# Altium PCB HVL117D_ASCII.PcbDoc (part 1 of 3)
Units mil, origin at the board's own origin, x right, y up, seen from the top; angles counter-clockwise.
Board outline 2004.03 x 2004.03 mil, 6 copper layers (Top Layer, InternalPlane1, MidLayer1, InternalPlane2, MidLayer2, Bottom Layer), stack 60.56 mil thick; 218 components, 157 nets, 658 pads, 273 vias.
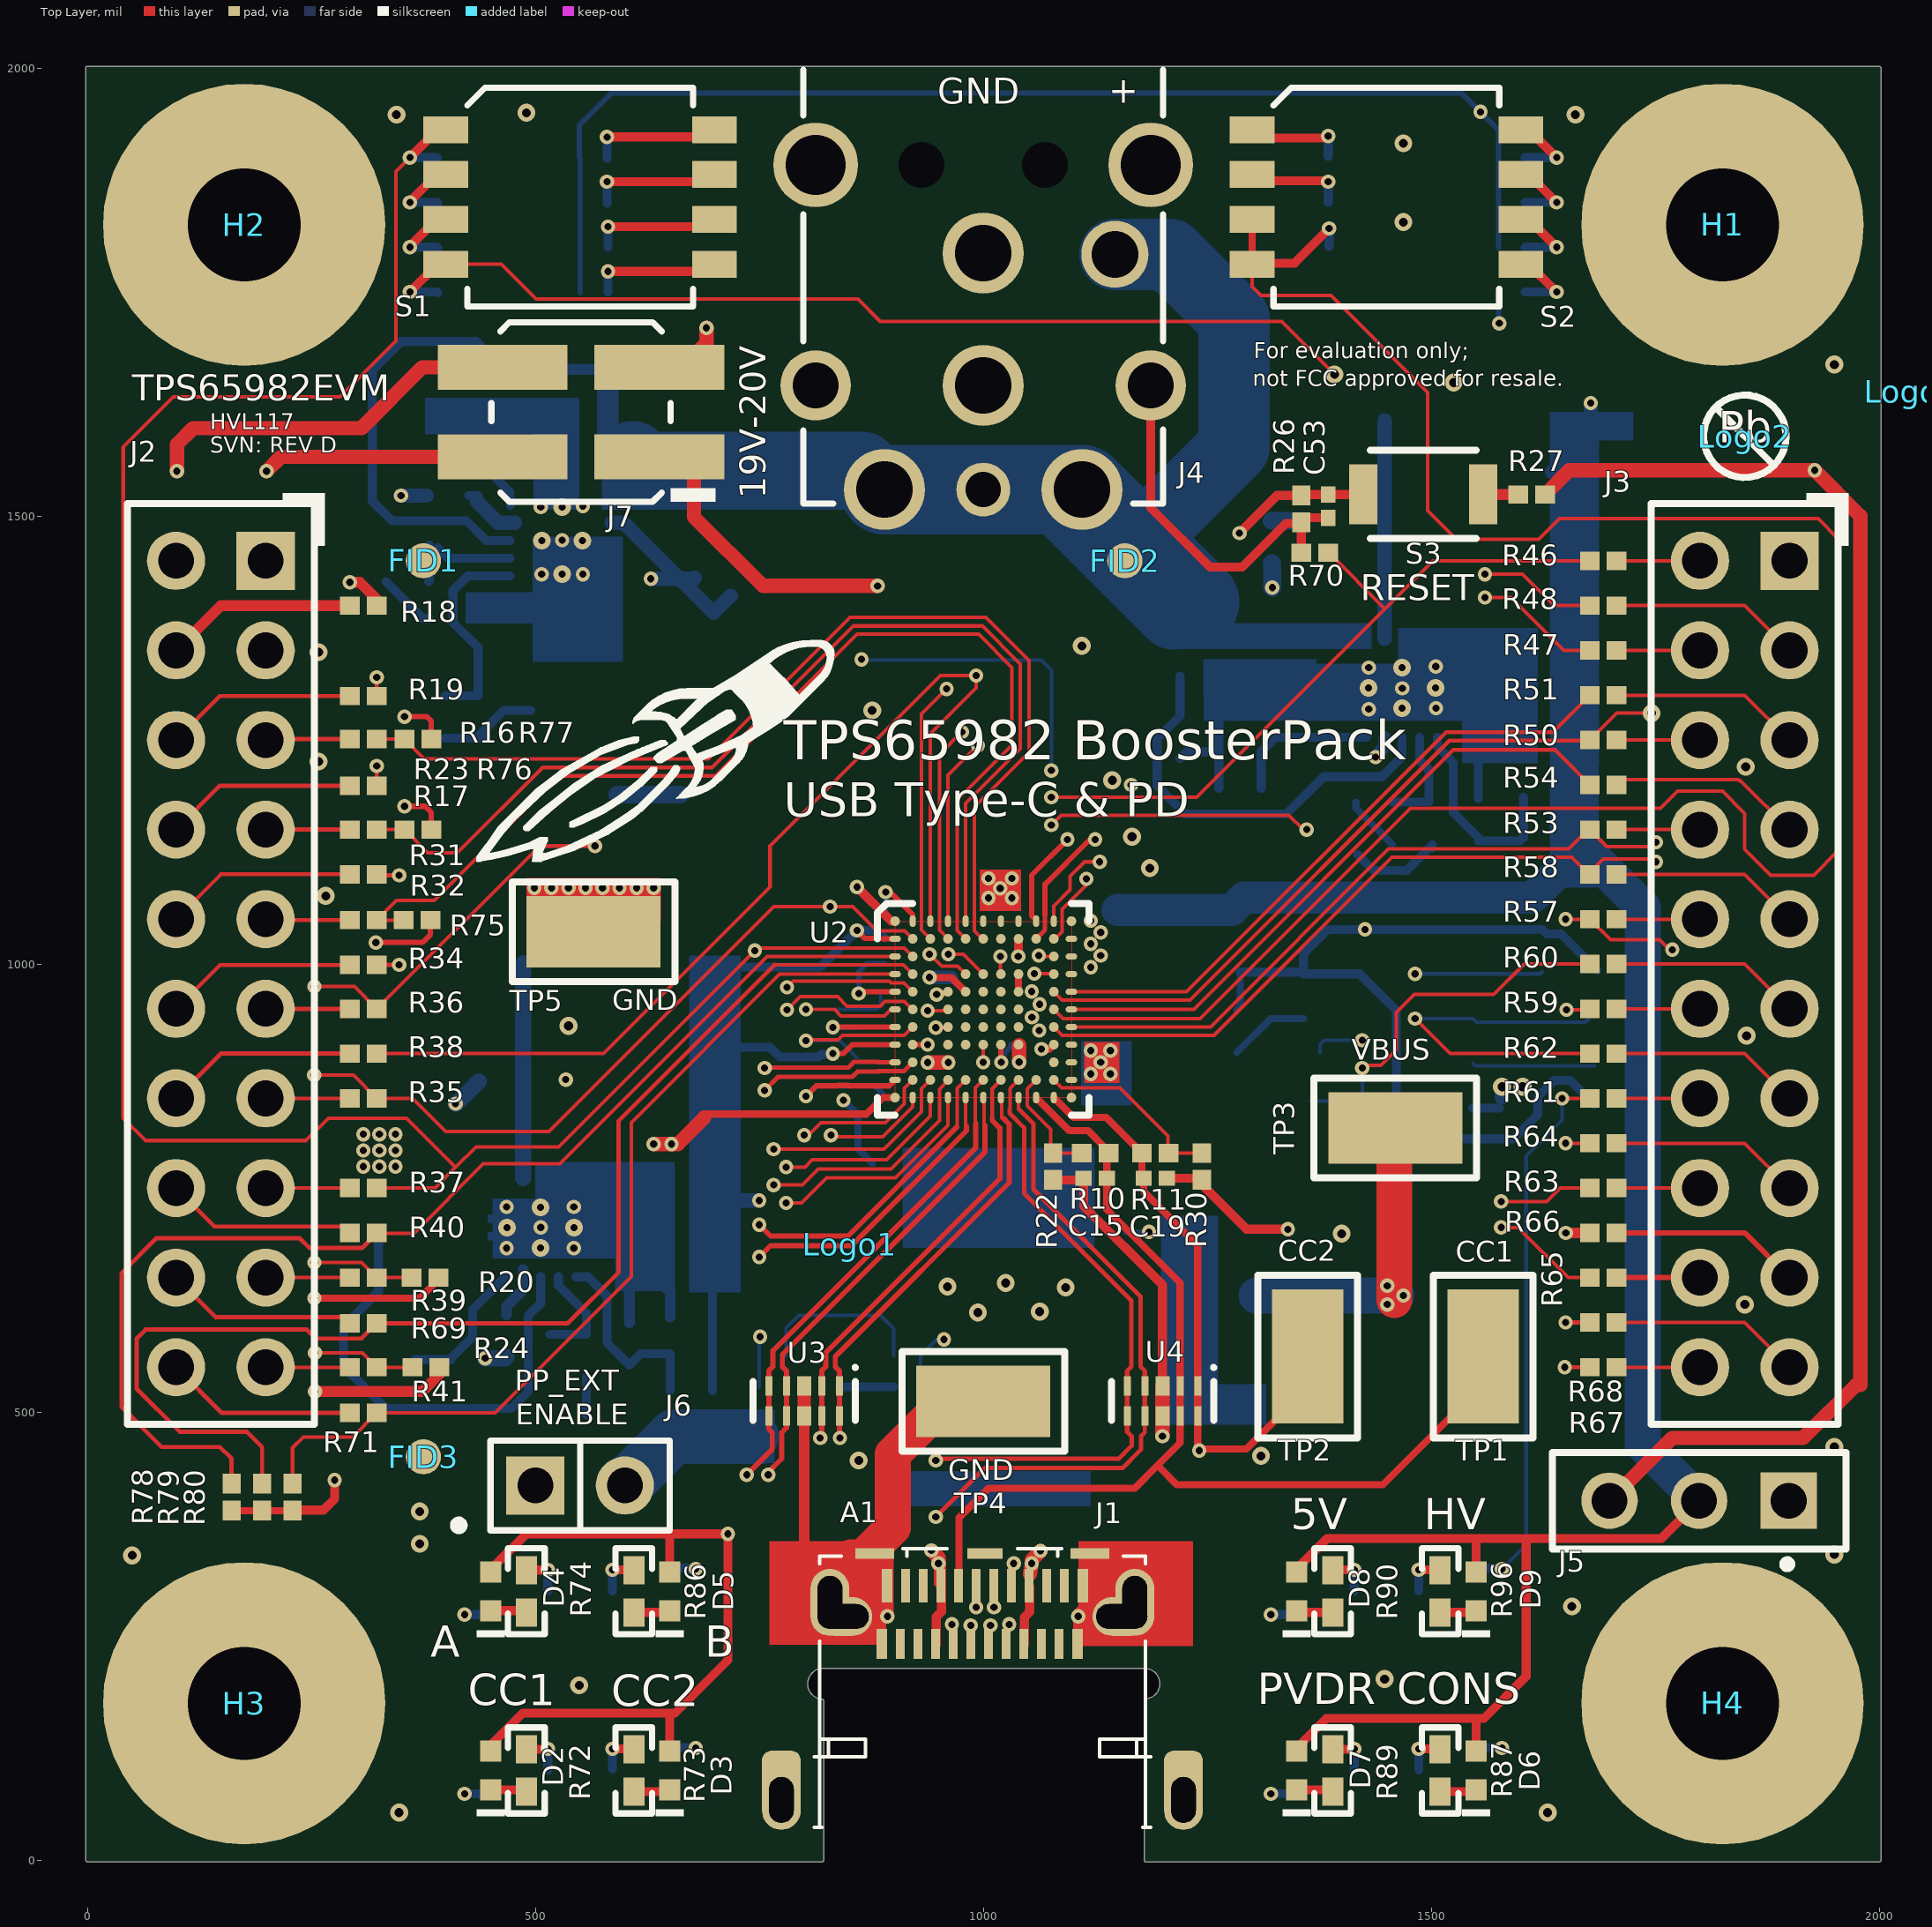
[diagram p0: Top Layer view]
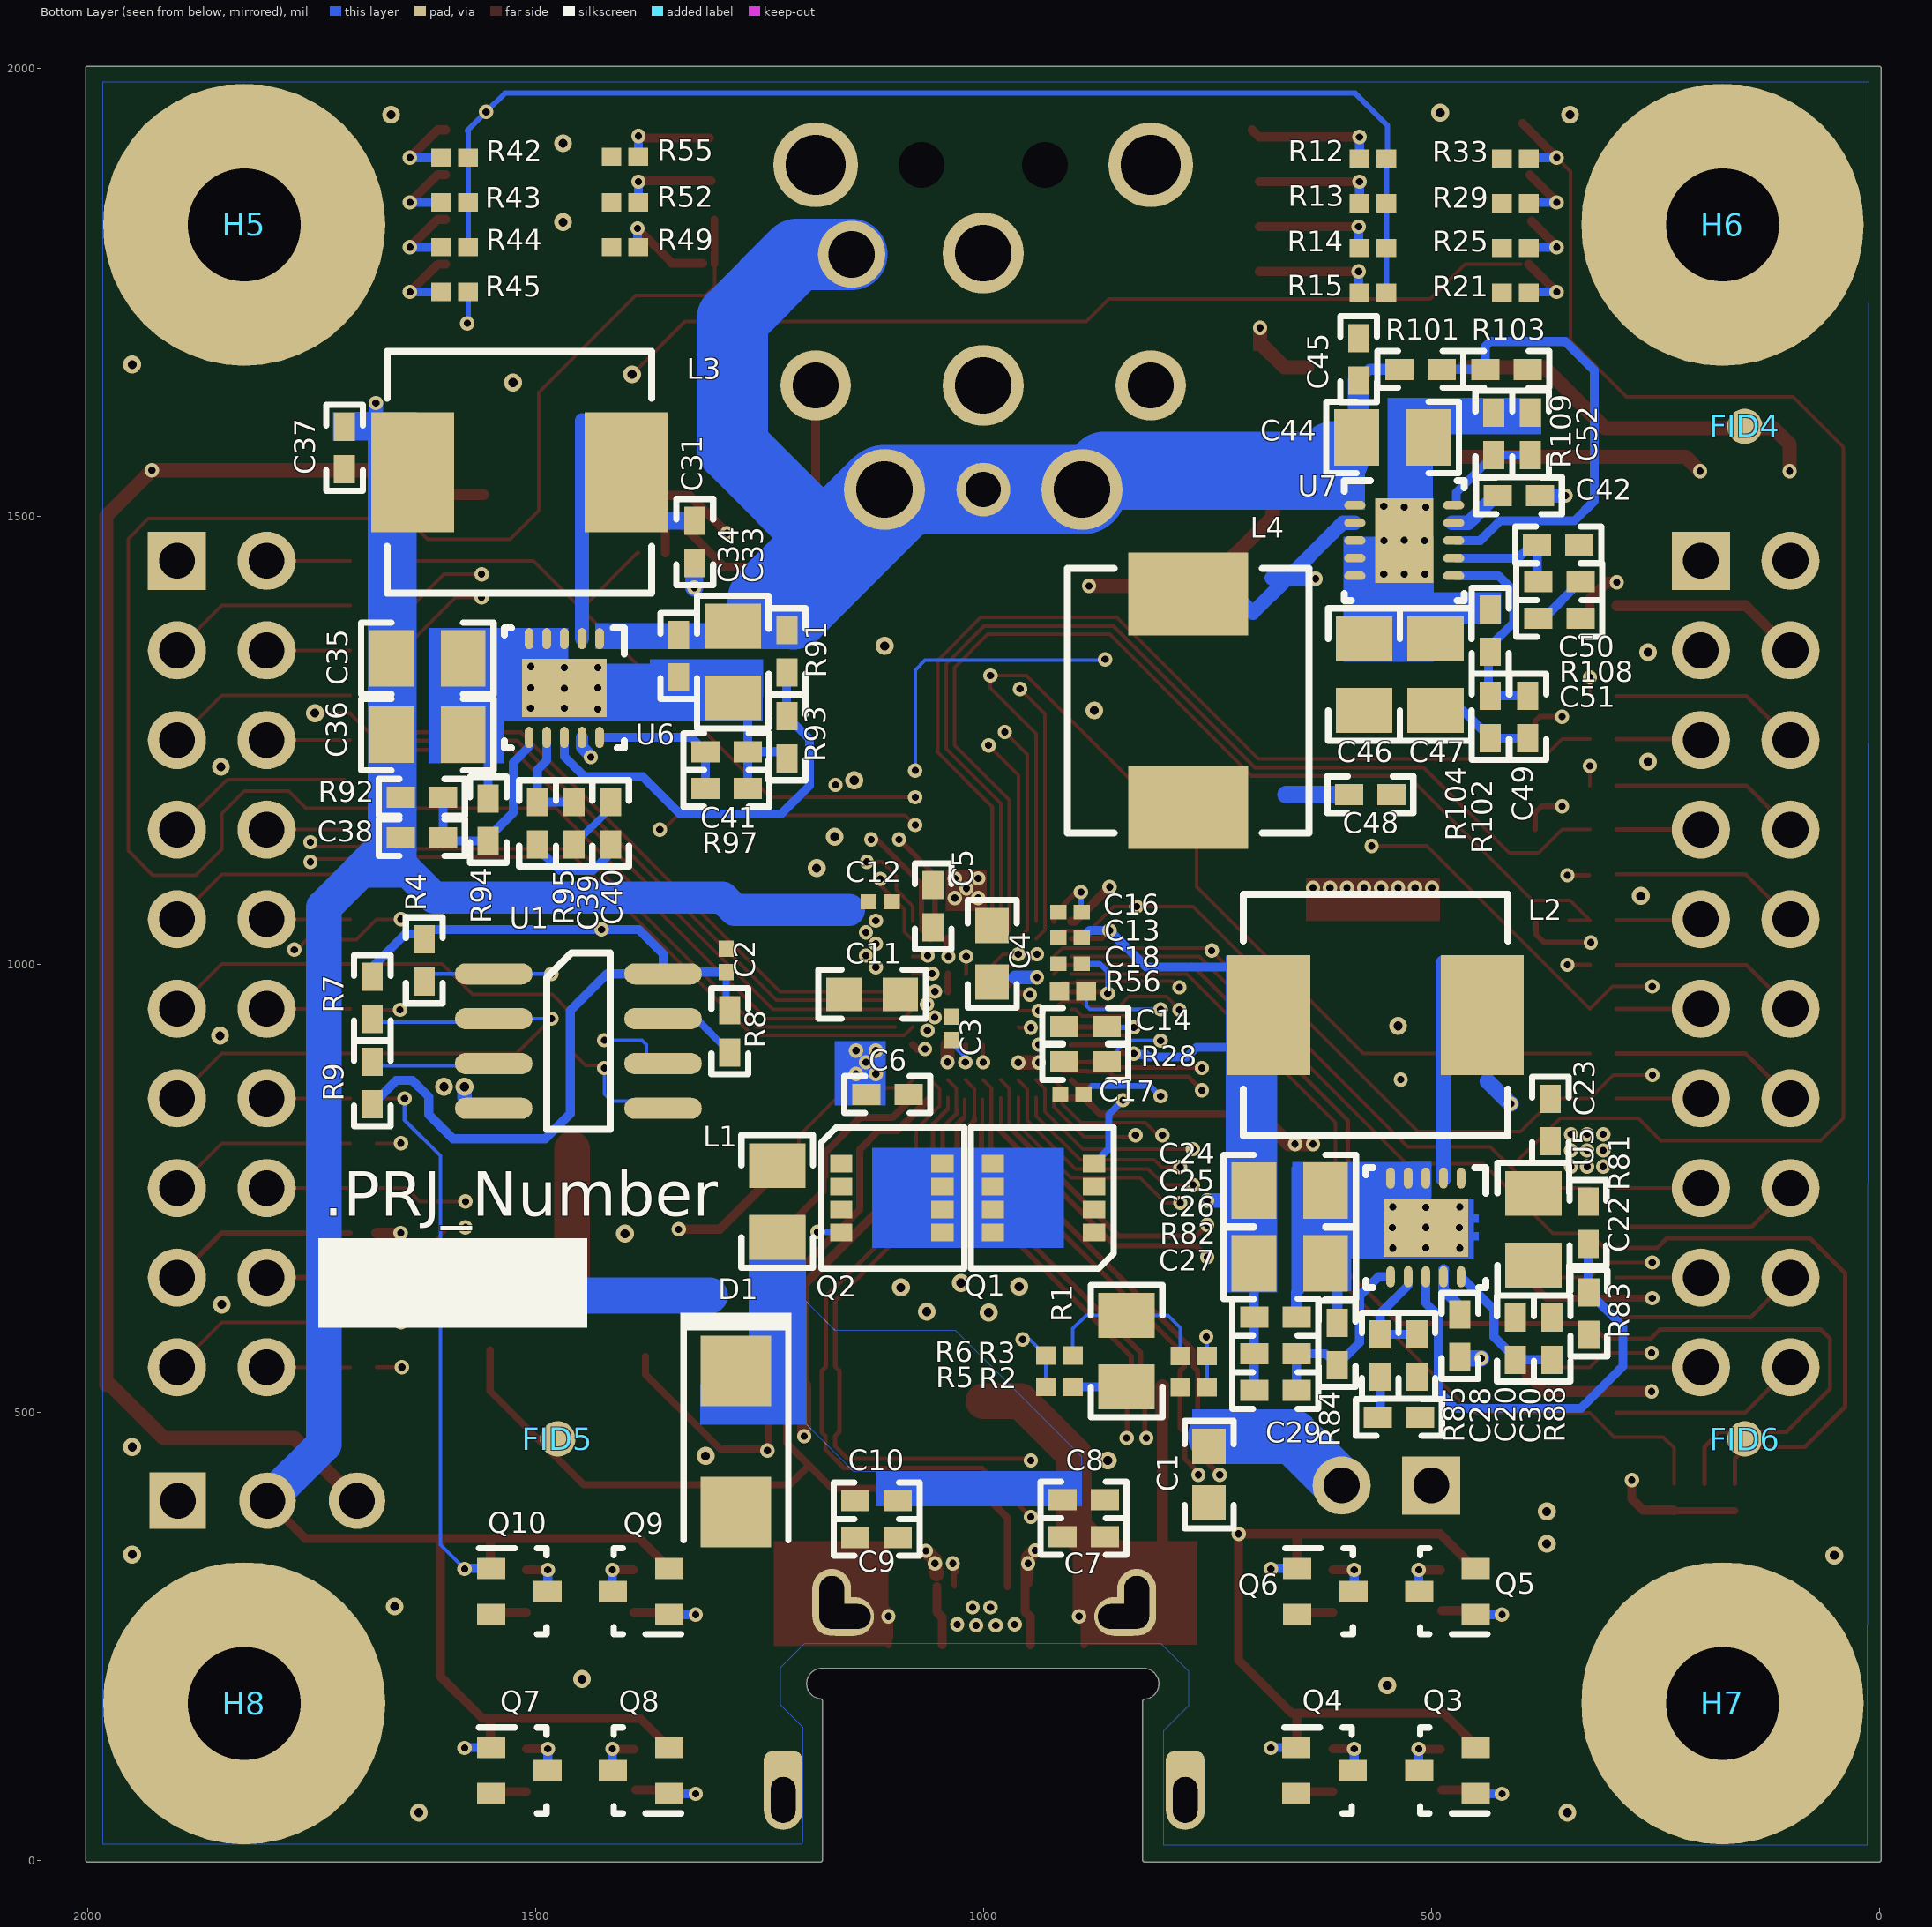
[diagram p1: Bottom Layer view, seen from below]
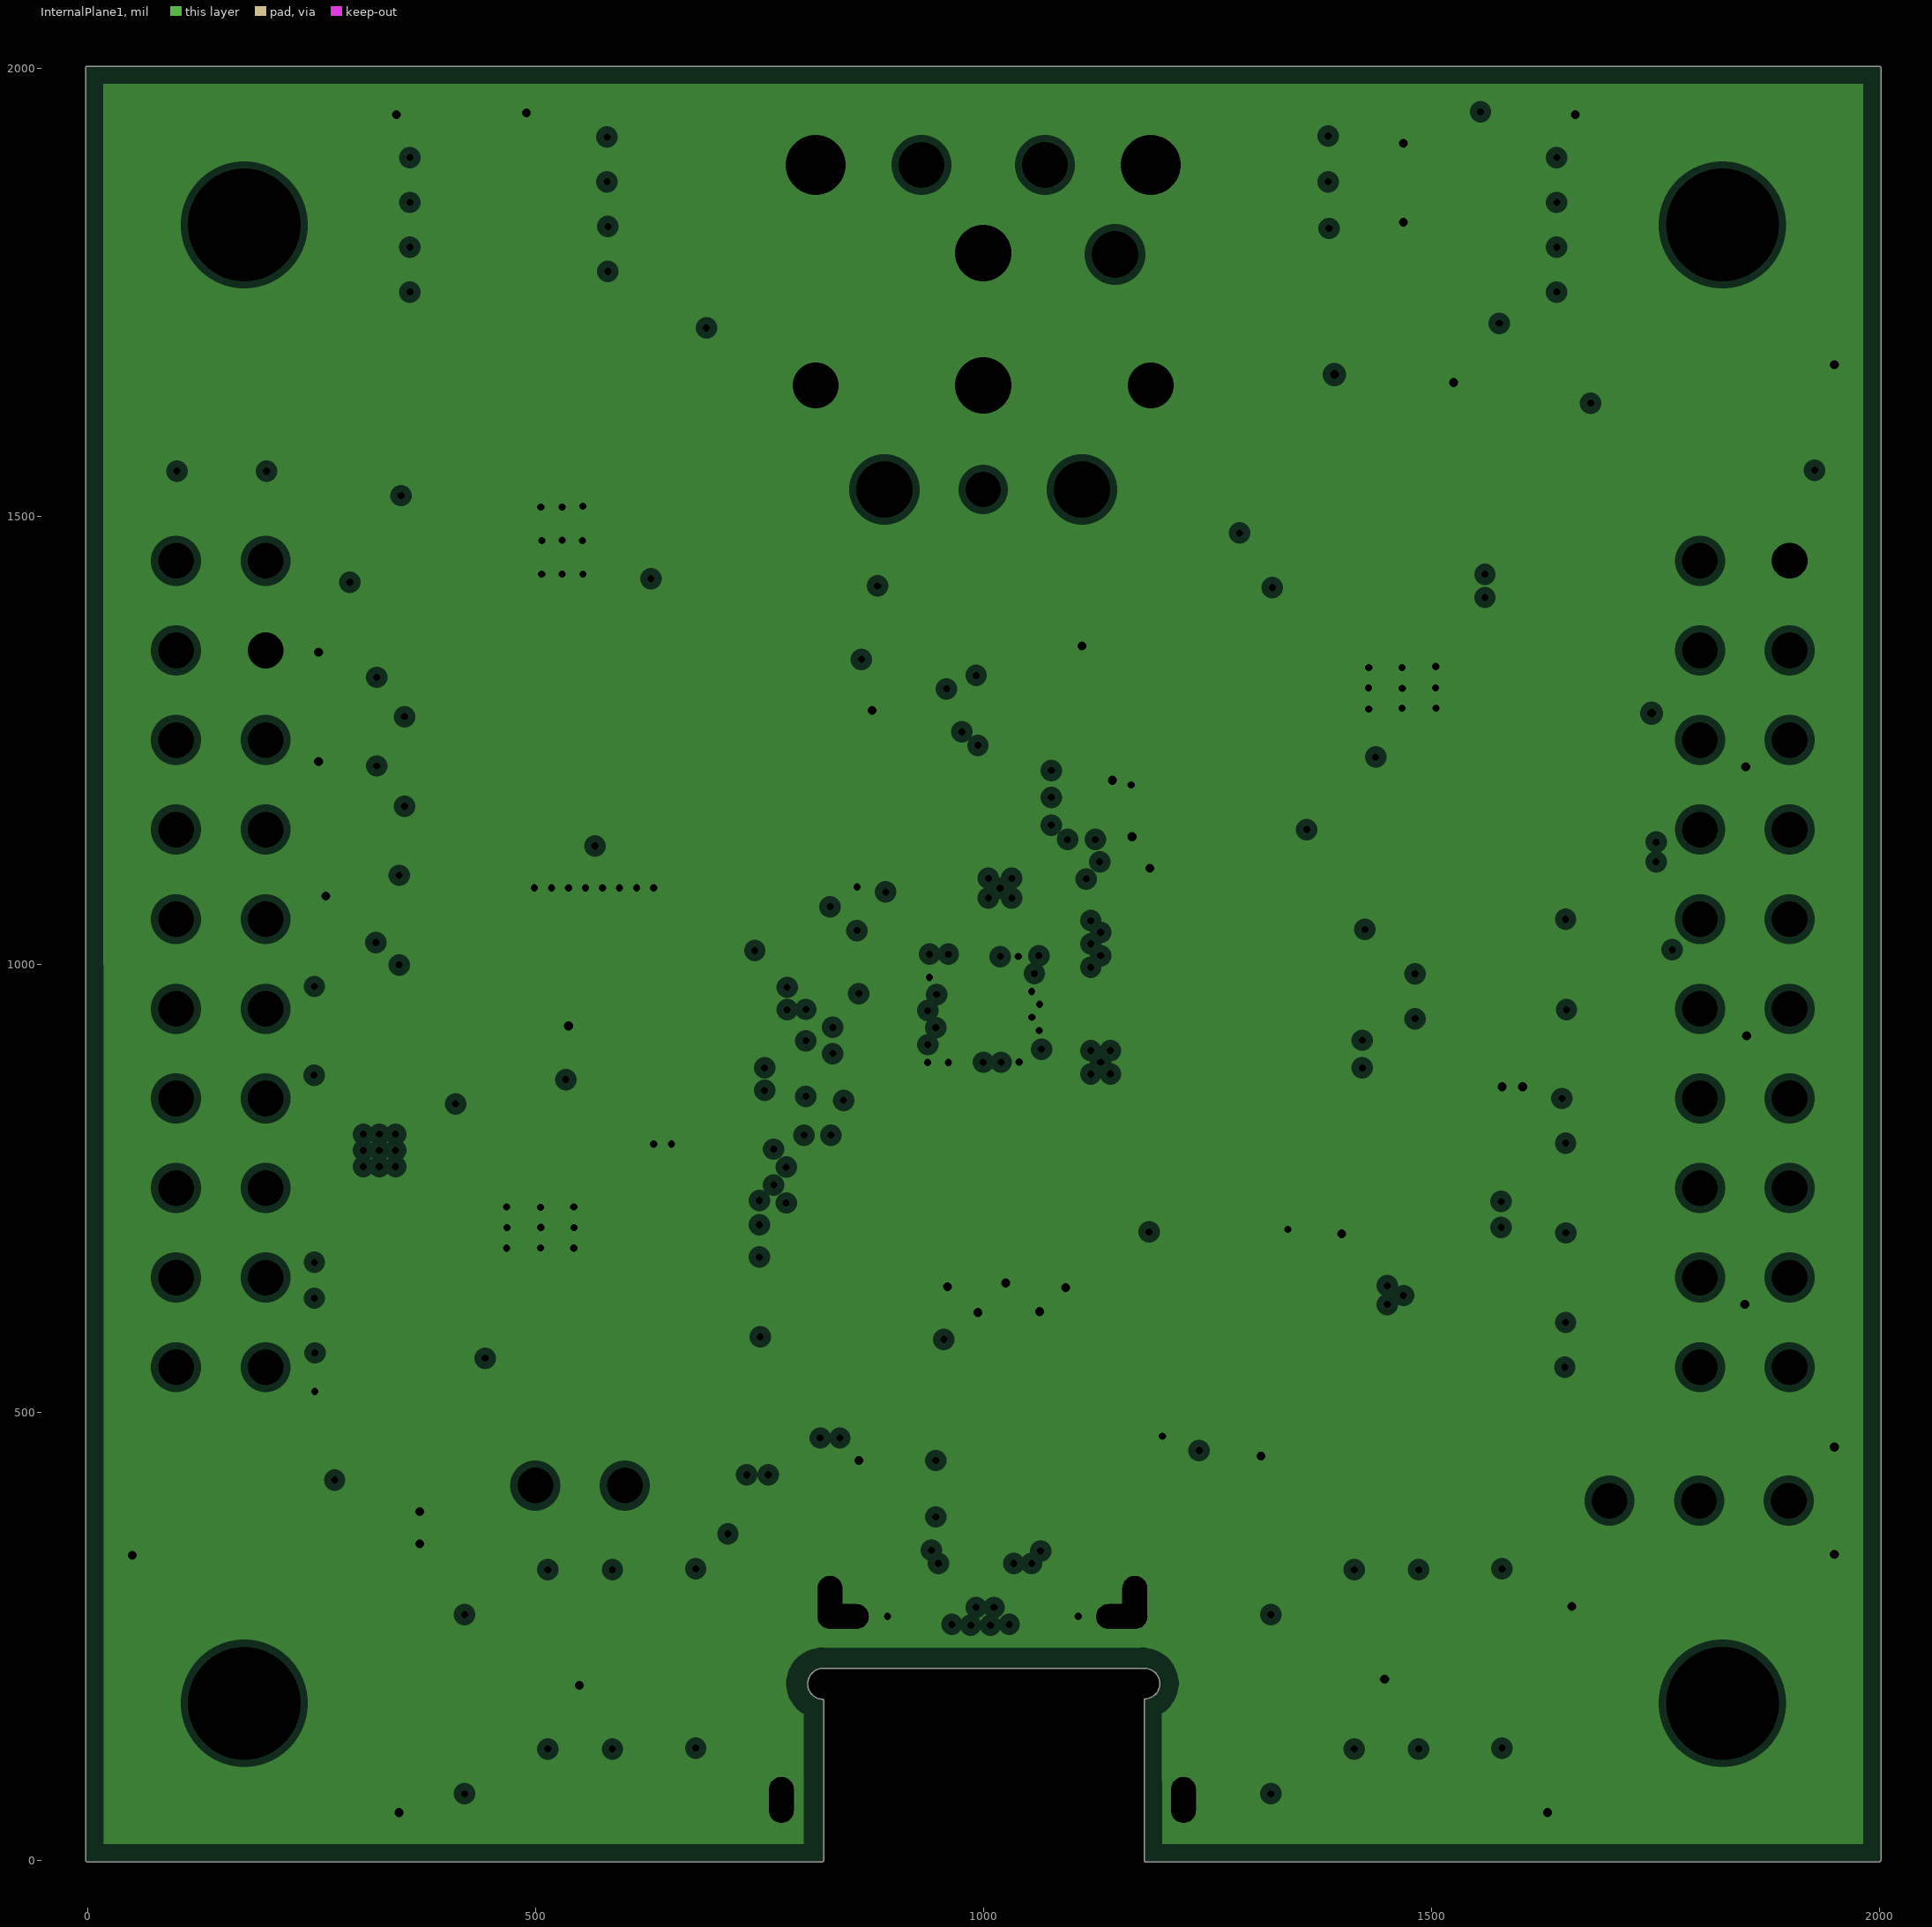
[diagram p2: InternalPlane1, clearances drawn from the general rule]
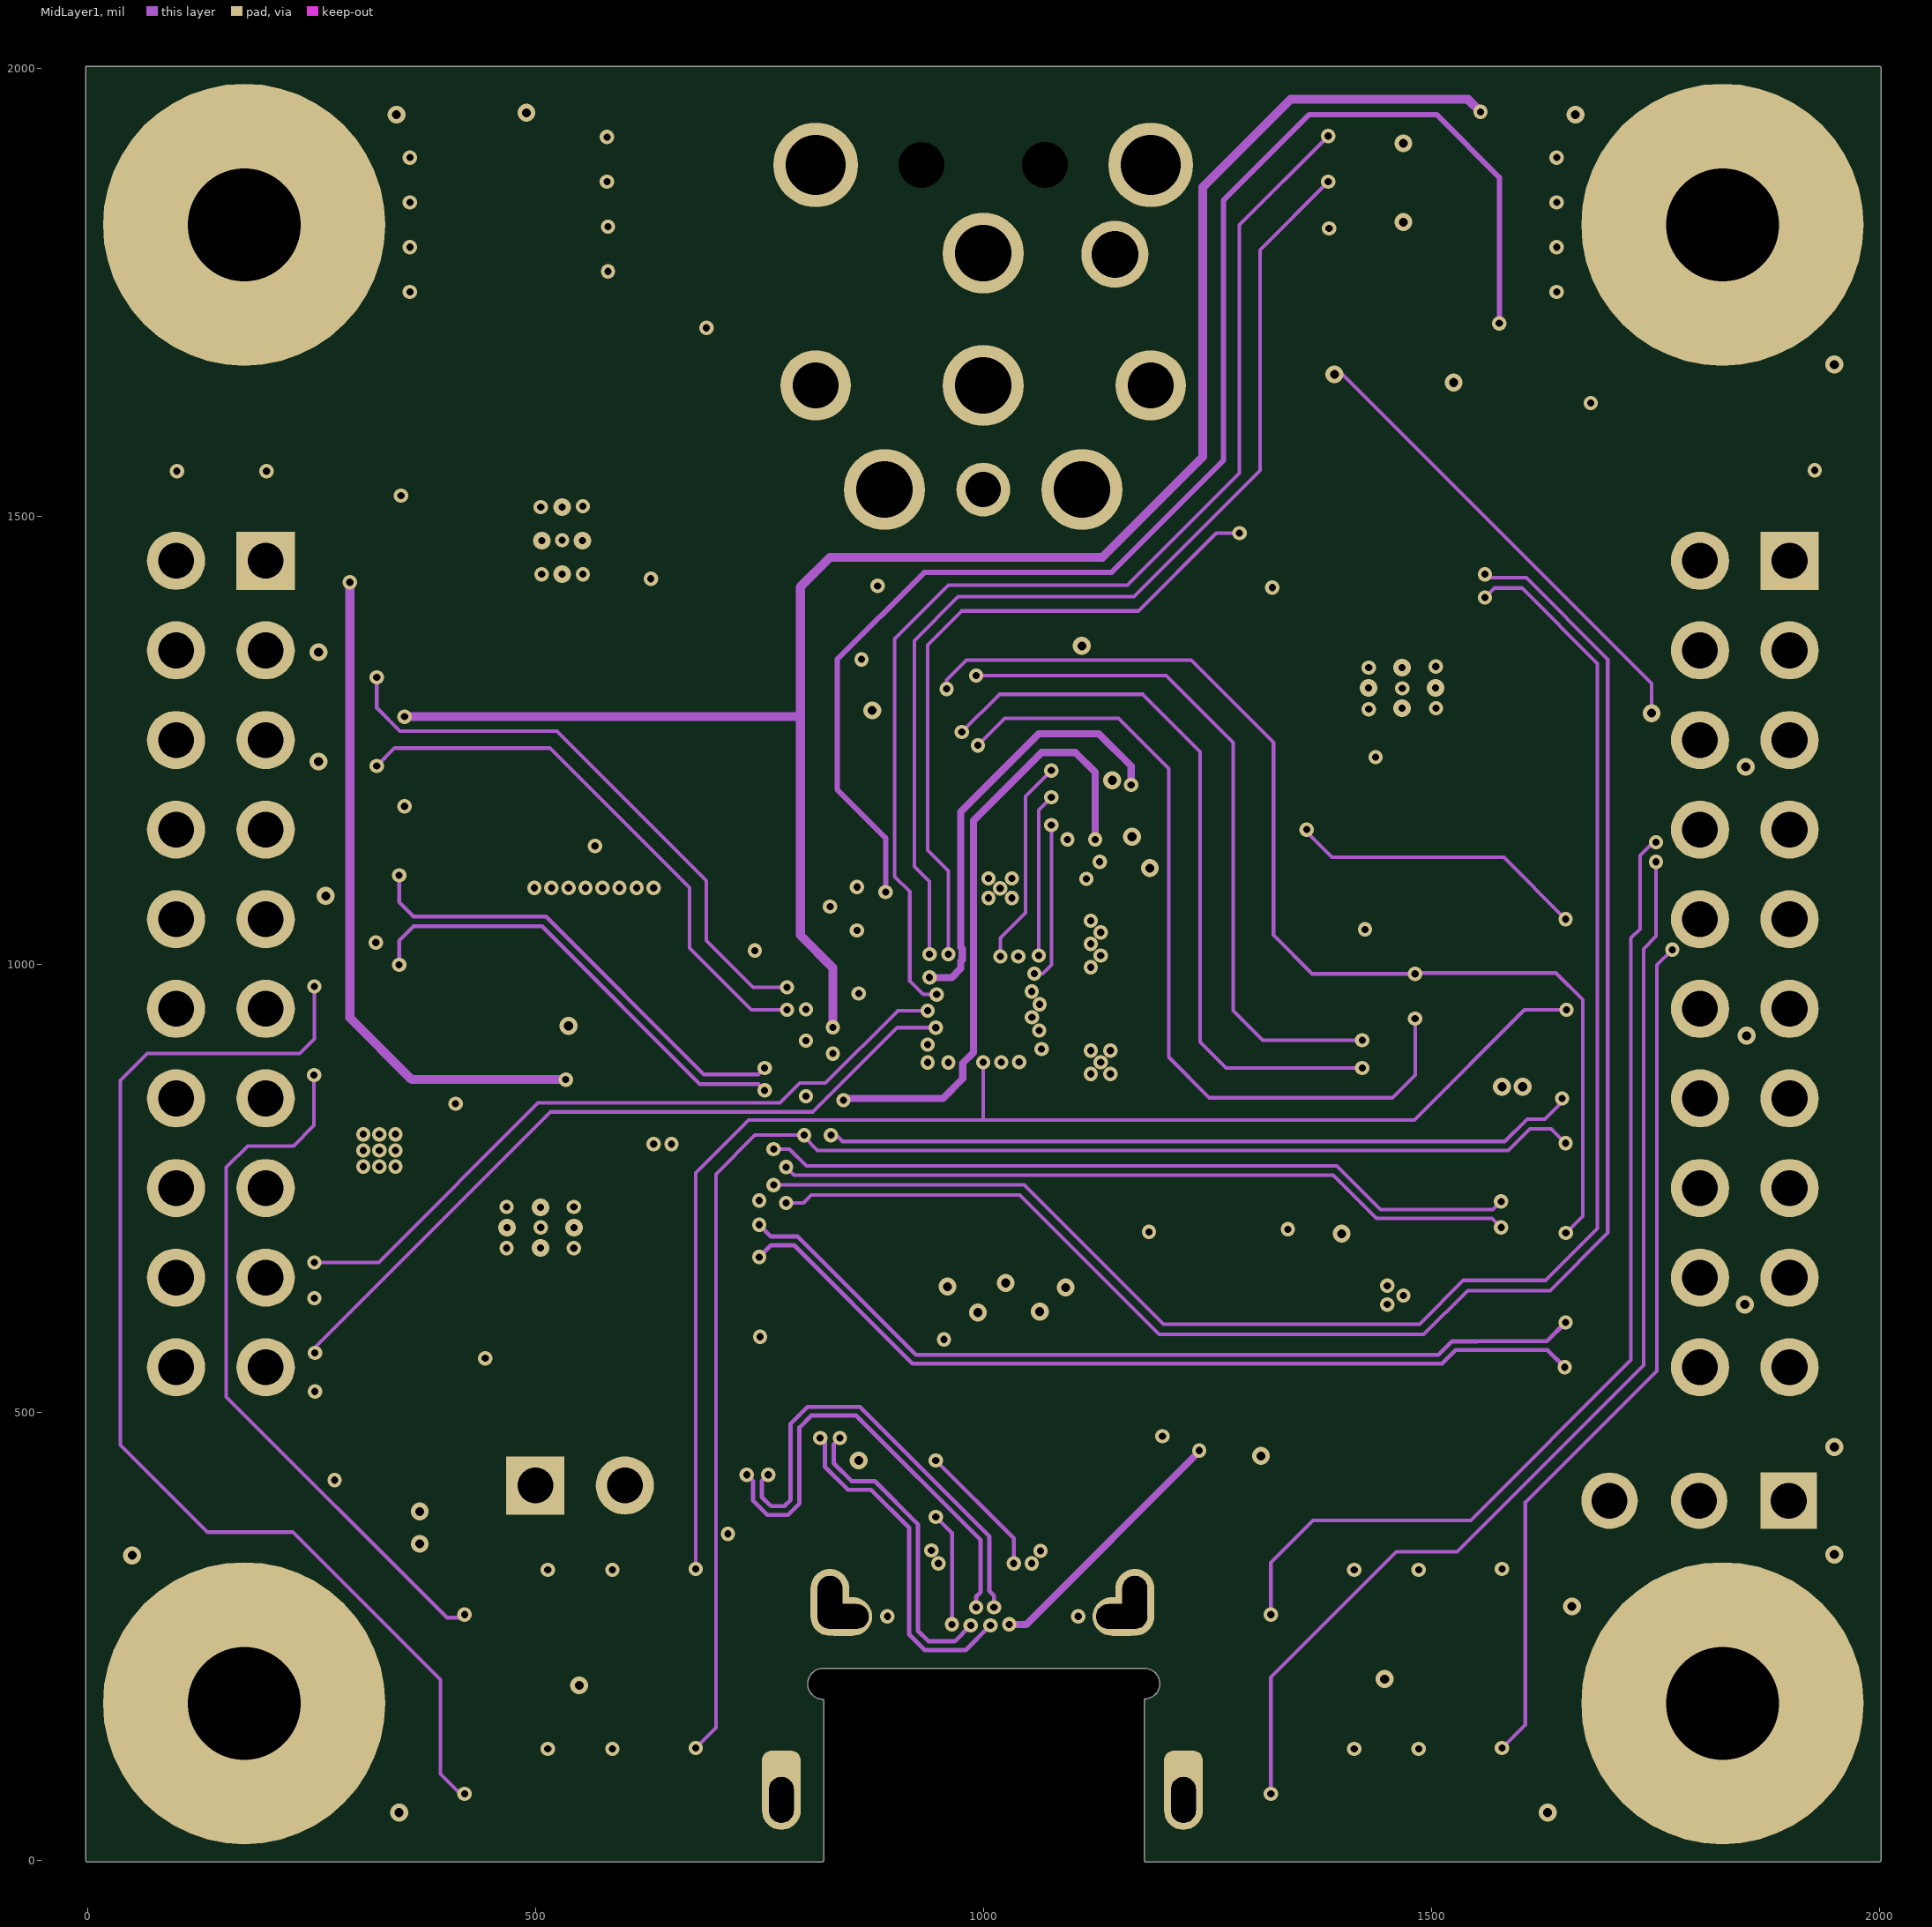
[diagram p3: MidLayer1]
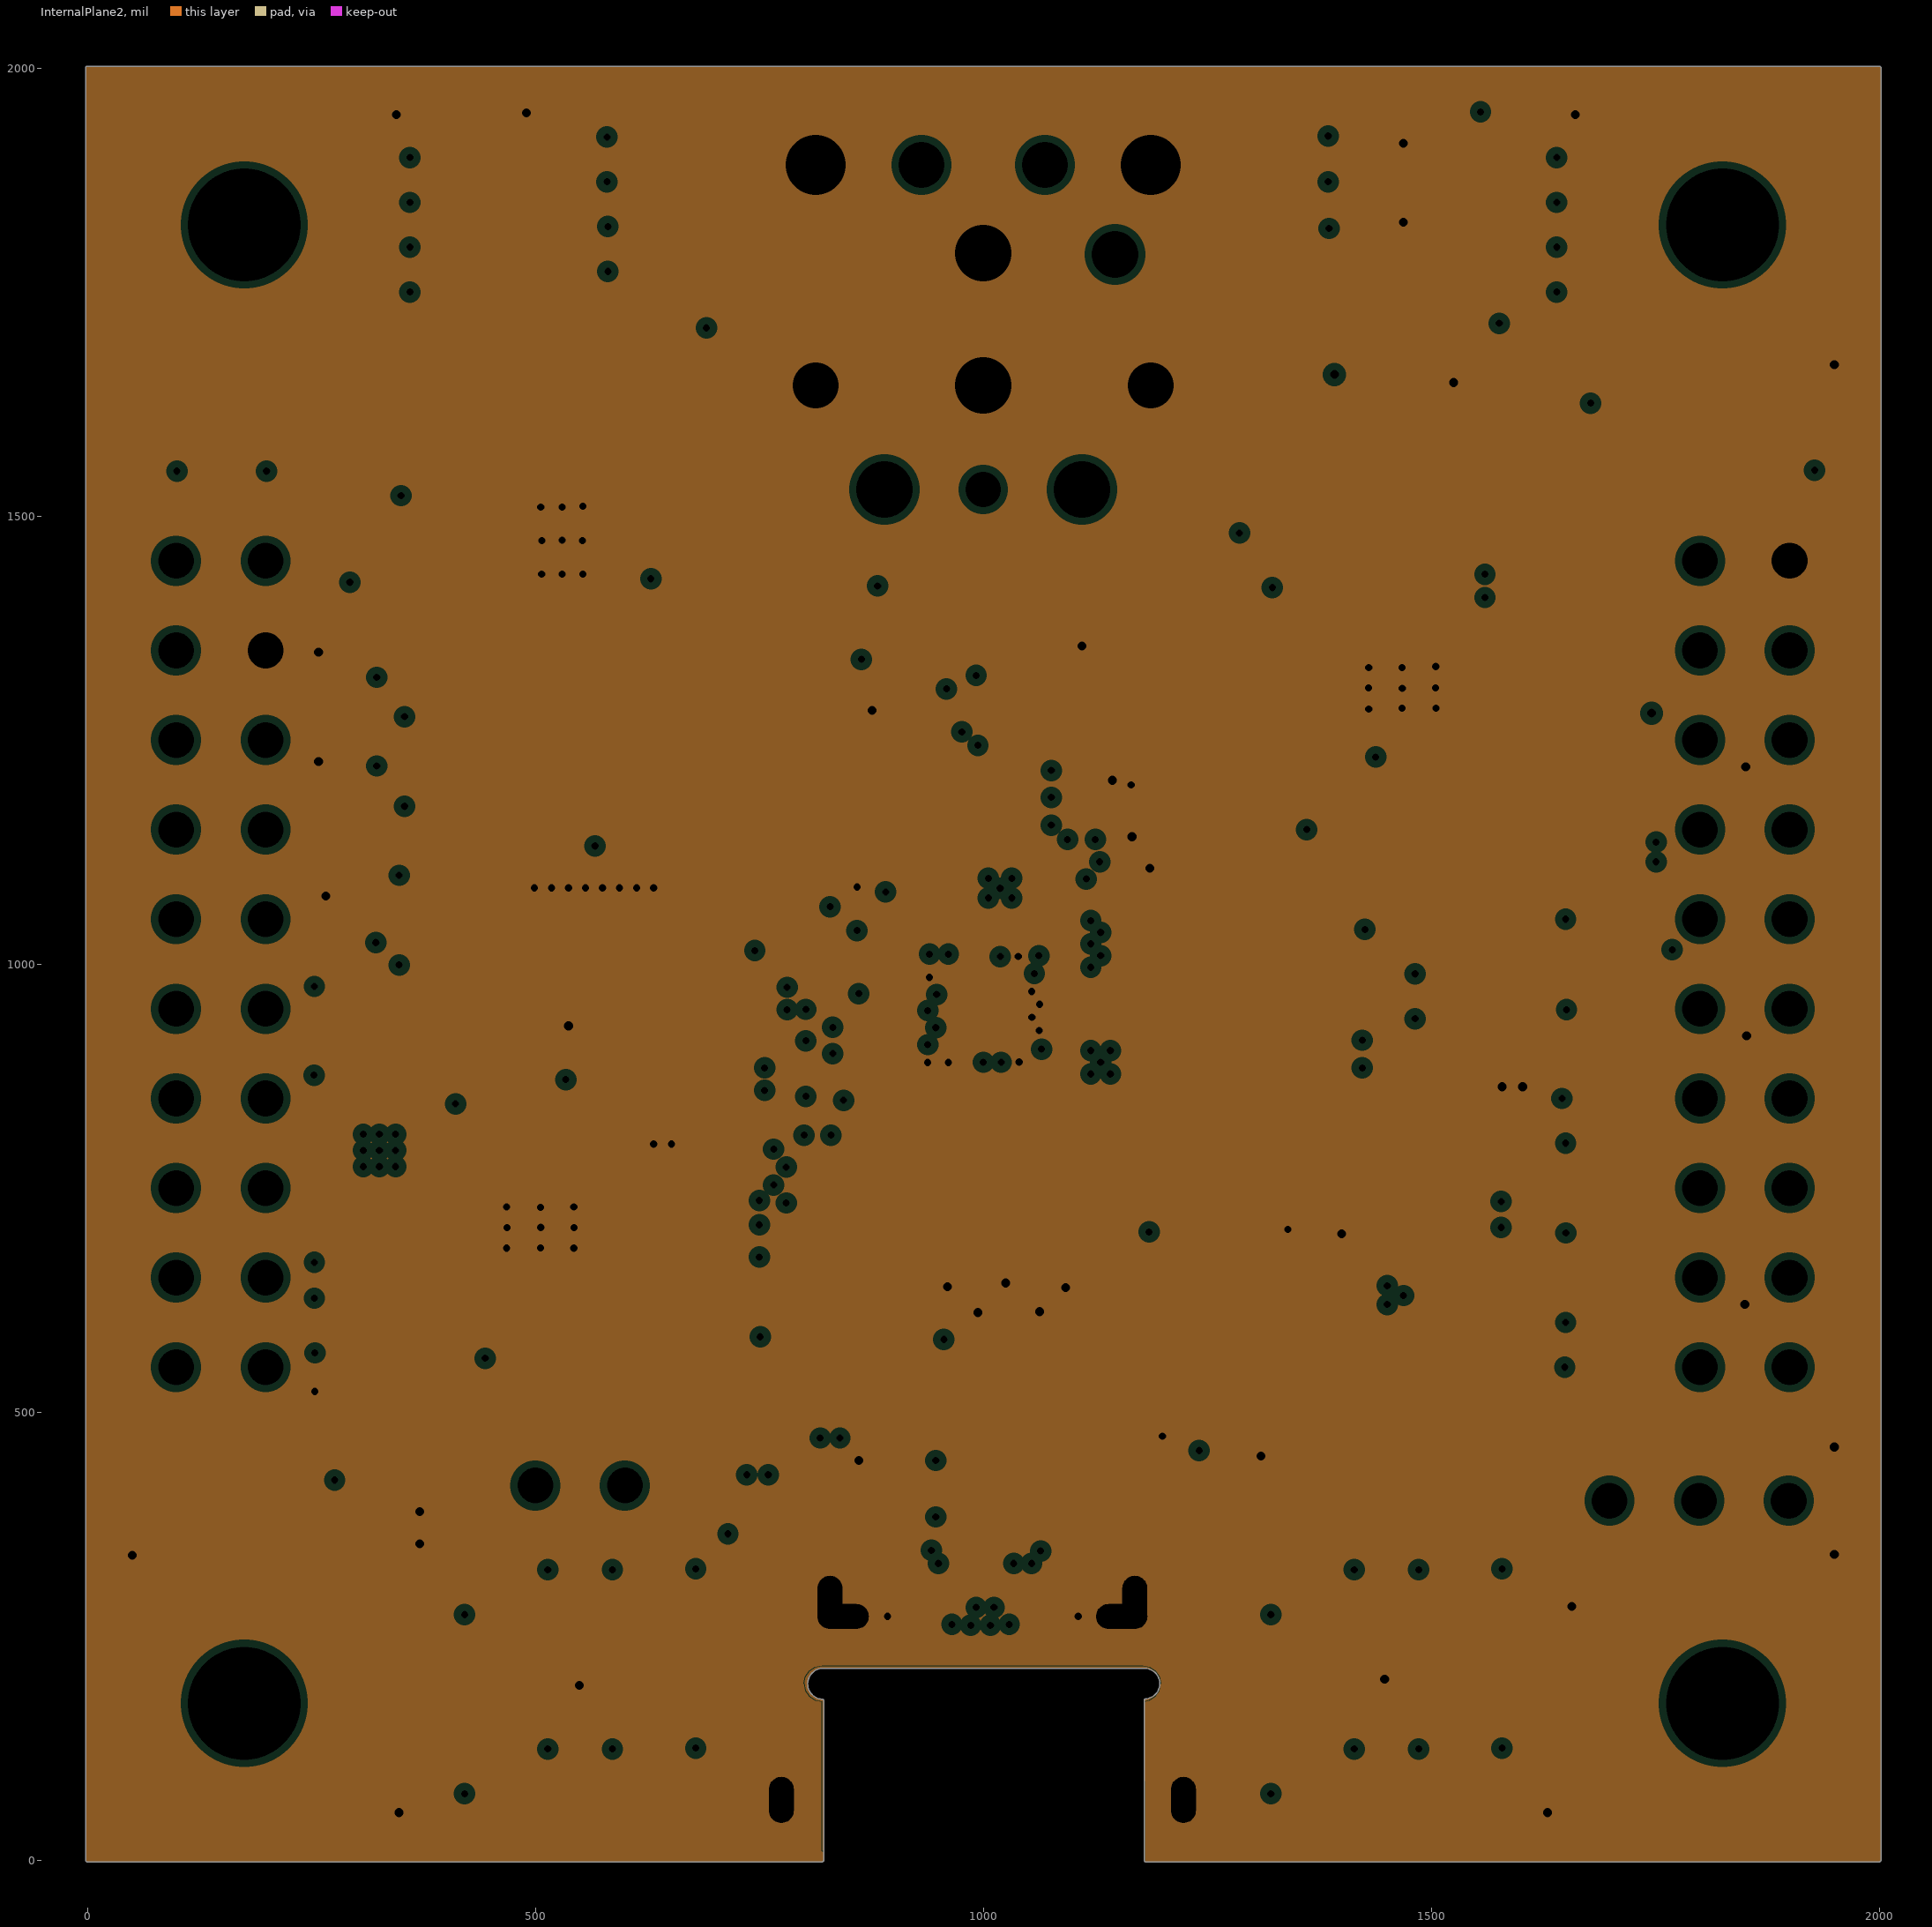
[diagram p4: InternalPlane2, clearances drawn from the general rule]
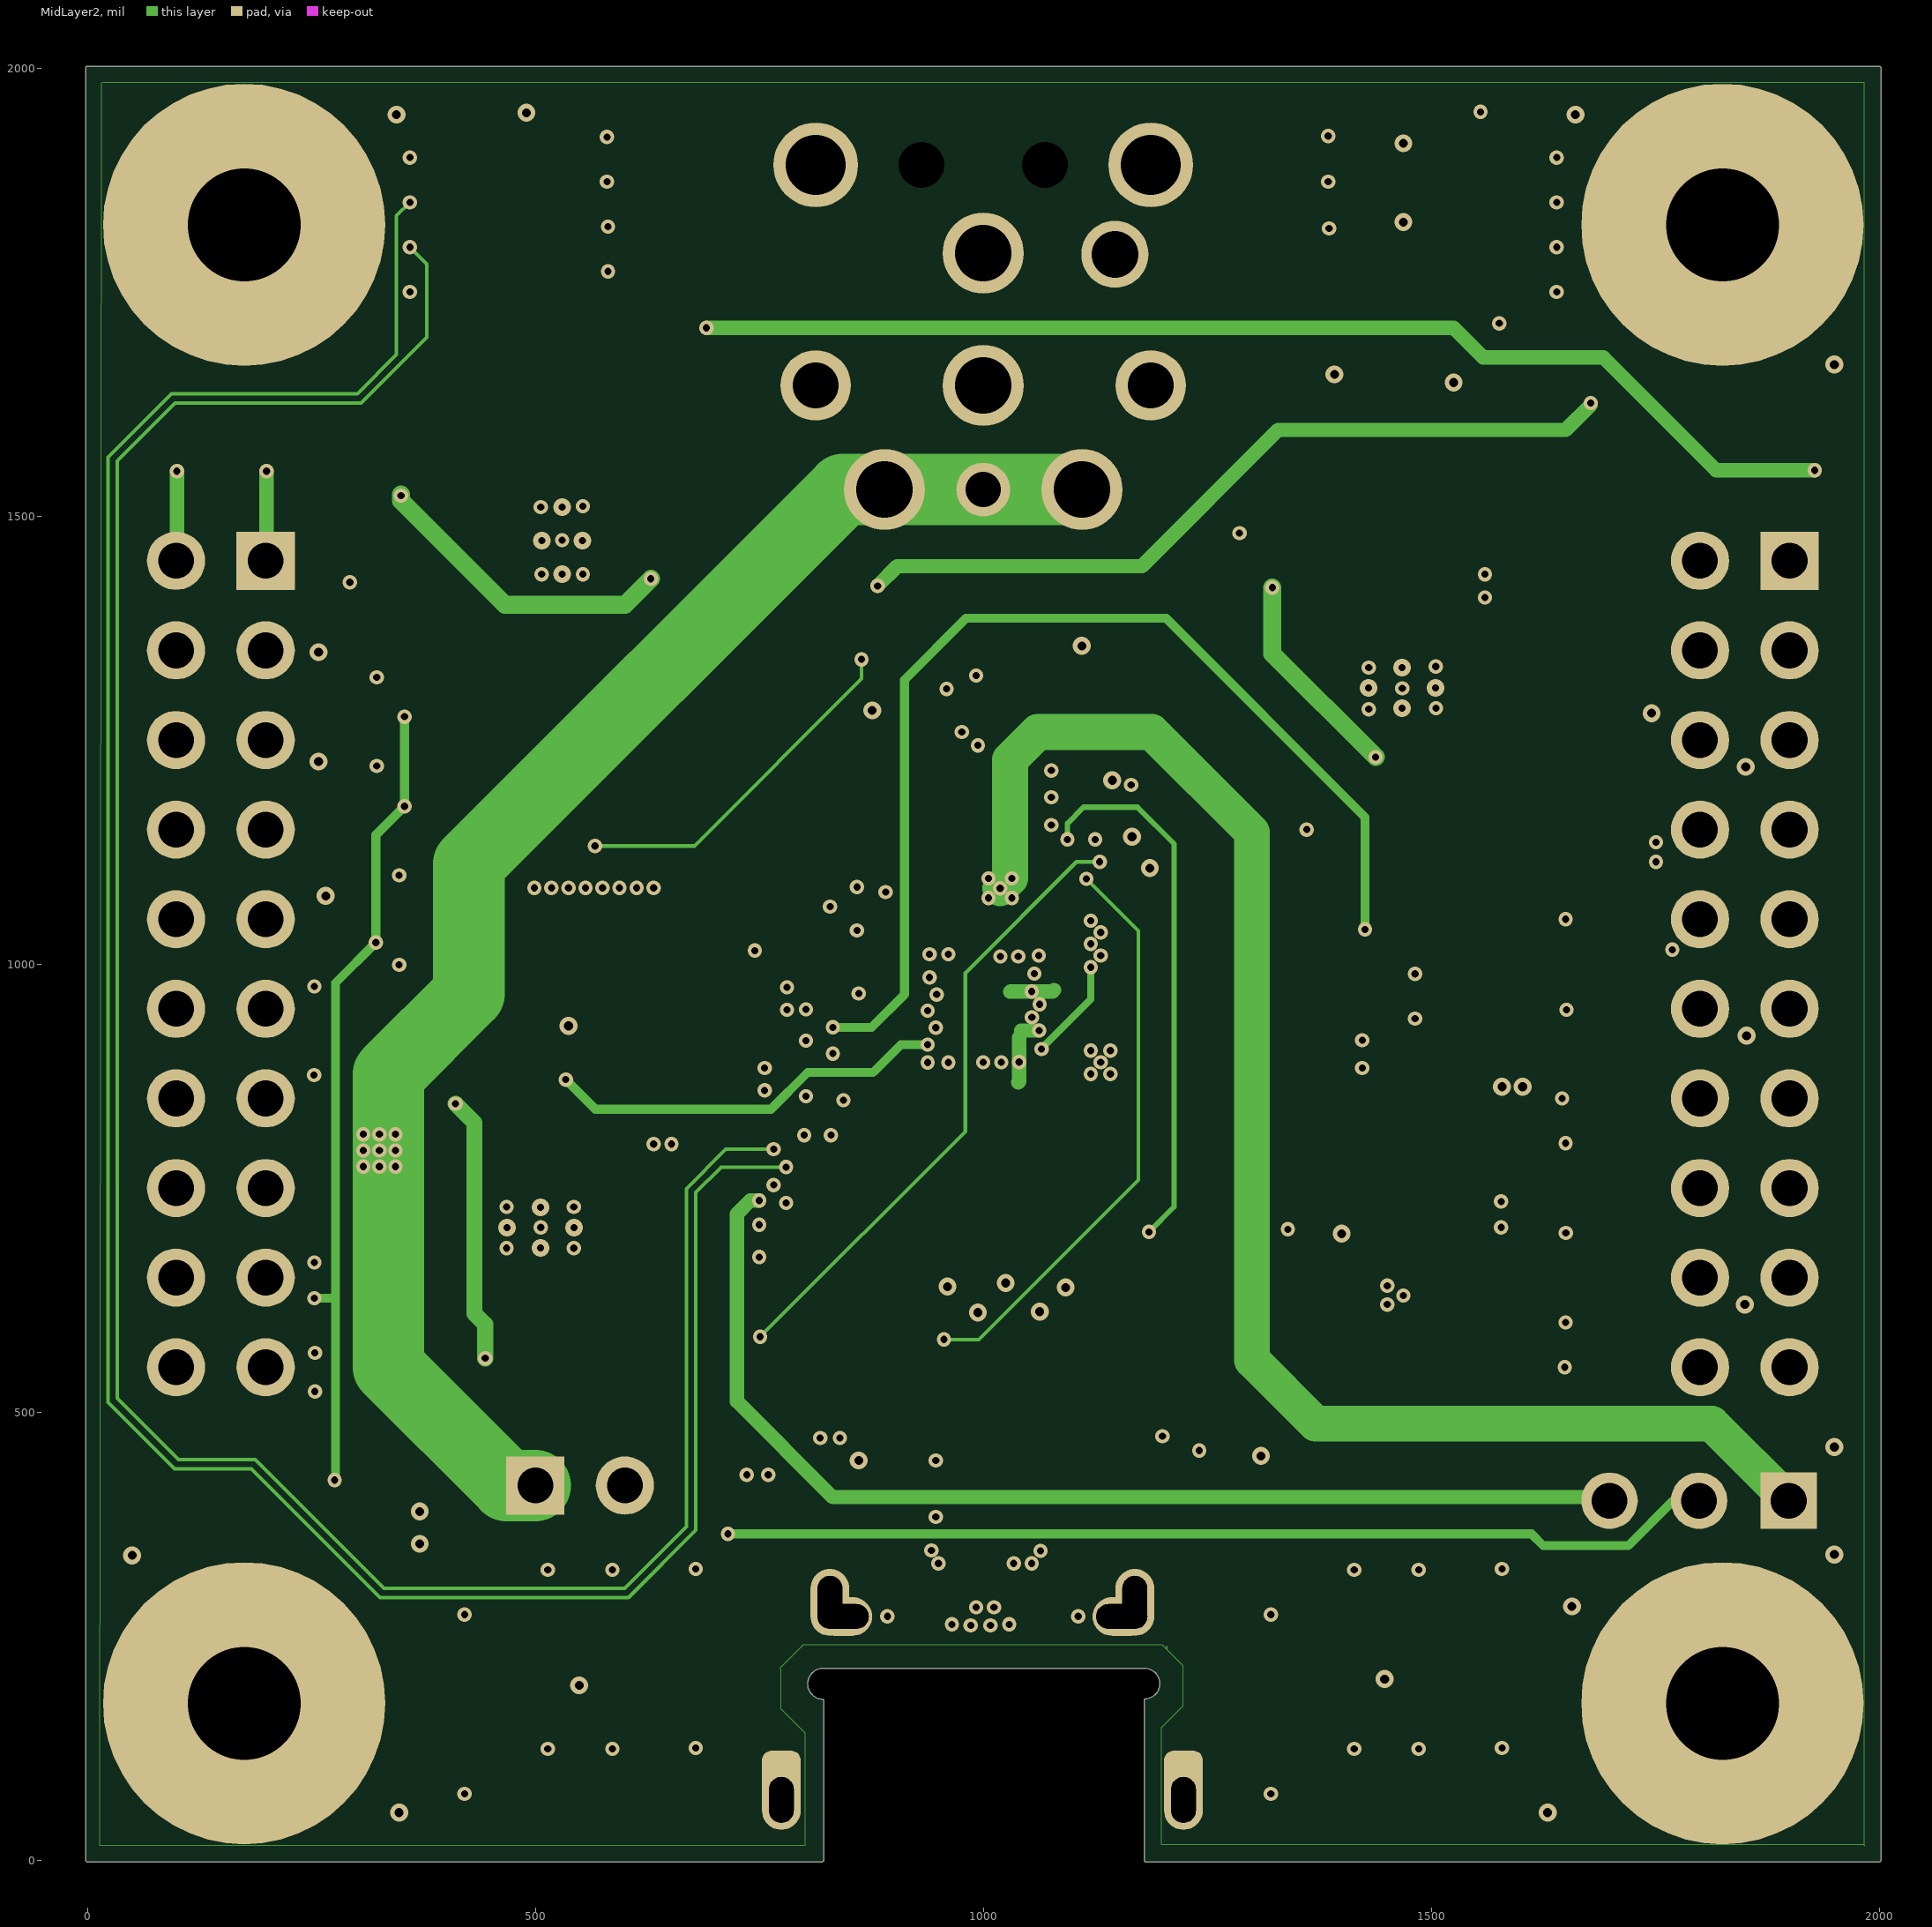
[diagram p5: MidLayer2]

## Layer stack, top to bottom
Top Solder: solder mask 0.8, Solder Resist, Dk 3.3
Top Layer: signal copper 1.4
Dielectric1: core 5.91, FR-4, Dk 4.1
InternalPlane1: plane copper 1.4, net GND
Dielectric4: prepreg 7.87, FR-4, Dk 4.1
MidLayer1: signal copper 1.4
Dielectric2: core 24.6, FR-4, Dk 4.1
InternalPlane2: plane copper 1.4, net GND
Dielectric5: prepreg 7.87, FR-4, Dk 4.1
MidLayer2: signal copper 1.4
Dielectric3: core 5.91, FR-4, Dk 4.1
Bottom Layer: signal copper 1.4
Bottom Solder: solder mask 0.8, Solder Resist, Dk 3.3

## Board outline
0,-2.02 cw(c0,0) -2.01,0 -2.01,2000 cw(c0,2000) 0,2002.01 2000,2002.01 cw(c2000,2000) 2002.01,2000 2002.01,0 cw(c2000,0) 2000,-2.02 1181.57,-2.02 cw(c1181.57,0) 1179.56,0 1179.56,176.43 cw(c1181.57,176.43) 1179.7,177.16 cw(c1181.59,177.86) 1181.42,179.86 ccw(c1180,196.89) 1197.09,196.89 ccw(c1180,196.89) 1180,213.98 821.31,213.98 ccw(c821.31,216) 821.33,213.98 821.31,213.98 ccw(c821.31,196.68) 819.21,179.51 cw(c818.96,177.51) 819.48,179.46 cw(c820,177.51) 822.02,177.51 822.02,0 cw(c820,0) 820,-2.02

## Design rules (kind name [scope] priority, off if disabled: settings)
AcuteAngle [All] p0: scope1count=1 scope1_0_kind=Board scope1_0_value=Board scope2count=1 scope2_0_kind=Board scope2_0_value=Board commentlength=0 minimum=4.50000000000000E+0001
AcuteAngle [All] p1: minimum=4.50000000000000E+0001 checktracksonly=FALSE
AssemblyTestPointUsage [All] p0: scope1count=1 scope1_0_kind=Board scope1_0_value=Board scope2count=1 scope2_0_kind=Board scope2_0_value=Board commentlength=0
AssemblyTestPointUsage [All] p1: valid=2
AssemblyTestpoint [All] p0: scope1count=1 scope1_0_kind=Board scope1_0_value=Board scope2count=1 scope2_0_kind=Board scope2_0_value=Board commentlength=0
Clearance Clearance_BoardEdge_MountingHoles [All] p0 off: scope1count=1 scope1_0_kind=Board scope1_0_value=Board scope2count=1 scope2_0_kind=Board scope2_0_value=Board commentlength=48 gap=15 // Protel DXP Scope 2 Expression Was: IsKeepOut
Clearance Clearance_BoardEdge_Poly [All] p0 off: scope1count=1 scope1_0_kind=Board scope1_0_value=Board scope2count=1 scope2_0_kind=Board scope2_0_value=Board commentlength=48 gap=25 // Protel DXP Scope 2 Expression Was: IsKeepOut
Clearance Clearance_BoardEdge [All] p0 off: scope1count=1 scope1_0_kind=Board scope1_0_value=Board scope2count=1 scope2_0_kind=Board scope2_0_value=Board commentlength=48 gap=5 // Protel DXP Scope 2 Expression Was: IsKeepOut
Clearance Clearance_Poly [All] p0 off: scope1count=1 scope1_0_kind=Board scope1_0_value=Board scope2count=1 scope2_0_kind=Board scope2_0_value=Board commentlength=48 gap=9 // Protel DXP Scope 1 Expression Was: InPolygon
Clearance [All] p0: scope1count=1 scope1_0_kind=Board scope1_0_value=Board scope2count=1 scope2_0_kind=Board scope2_0_value=Board commentlength=0 gap=3
Clearance Clearance_BoardEdge_MountingHoles [OnCopper and InComponentClass('Mounting Holes') vs IsKeepOut] p1: gap=15
Clearance Clearance_BoardEdge_Poly [OnCopper and InPoly vs IsKeepOut] p2: gap=25
Clearance Clearance_BoardEdge [OnCopper and Not InComponentClass('Logo') and not InComponentClass('FiducialMark') and not InRegion(1000,500,4000,800) and Not IsKeepout vs IsKeepOut] p3: gap=5
Clearance Clearance_Poly [InPolygon] p4: gap=9
Clearance [All] p5: gap=3
ComponentClearance ComponentClearance_Shunt [All] p0: scope1count=1 scope1_0_kind=ComponentClass scope1_0_value=Header scope2count=1 scope2_0_kind=ComponentClass scope2_0_value=Shunt commentlength=0 gap=0 collisioncheckmode=3
ComponentClearance ComponentClearance_MountingHoles_FiducialMarks [All] p0: scope1count=1 scope1_0_kind=ComponentClass scope1_0_value="Mounting Holes" scope2count=1 scope2_0_kind=ComponentClass scope2_0_value=FiducialMark commentlength=0 gap=50 collisioncheckmode=3
ComponentClearance ComponentClearance_Logo [All] p0: scope1count=1 scope1_0_kind=ComponentClass scope1_0_value=Logo scope2count=1 scope2_0_kind=Board scope2_0_value=Board commentlength=0 gap=0 collisioncheckmode=3
ComponentClearance ComponentClearance_ScrewToNut [All] p0 off: scope1count=1 scope1_0_kind=Board scope1_0_value=Board scope2count=1 scope2_0_kind=Board scope2_0_value=Board commentlength=71 gap=5 collisioncheckmode=3 // Protel DXP Scope 2 Expression Was: (HasFootprint('Keystone_1902C'))
ComponentClearance ComponentClearance_MountingHoles [All] p0: scope1count=1 scope1_0_kind=ComponentClass scope1_0_value="Mounting Holes" scope2count=1 scope2_0_kind=Board scope2_0_value=Board commentlength=0 gap=20 collisioncheckmode=3
ComponentClearance ComponentClearance_SmallPassives [All] p0 off: scope1count=1 scope1_0_kind=Board scope1_0_value=Board scope2count=1 scope2_0_kind=Board scope2_0_value=Board commentlength=508 gap=15 collisioncheckmode=3 // Protel DXP Scope 2 Expression Was: HasFootprint('0201*') or HasFootprint('0402*') or HasFootprint('0508') or HasFootprint('0603*') or HasFootprint('0612') or HasFootprint('0805*') or HasFootprint('0815*') or HasFootprint('0830*') or HasFootprint('1206*') or HasFootprint('1210*') or HasFootprint('1808*') or HasFootprint('1812*') or HasFootprint('1825*') or HasFootprint('2010*') or HasFootprint('2220*') or HasFootprint('2225*') or HasFootprint('2512*') or HasFootprint('2728*') or HasFootprint('3518*')
ComponentClearance ComponentClearance_THtoSMT [All] p0 off: scope1count=1 scope1_0_kind=Board scope1_0_value=Board scope2count=1 scope2_0_kind=Board scope2_0_value=Board commentlength=53 gap=20 collisioncheckmode=3 // Protel DXP Scope 2 Expression Was: IsSMTComponent
ComponentClearance ComponentClearance_THtoTH [All] p0 off: scope1count=1 scope1_0_kind=Board scope1_0_value=Board scope2count=1 scope2_0_kind=Board scope2_0_value=Board commentlength=54 gap=10 collisioncheckmode=3 // Protel DXP Scope 2 Expression Was: IsThruComponent
ComponentClearance [All] p0: scope1count=1 scope1_0_kind=Board scope1_0_value=Board scope2count=1 scope2_0_kind=Board scope2_0_value=Board commentlength=0 gap=15 collisioncheckmode=3
ComponentClearance ComponentClearance_Shunt [InComponentClass('Header') vs InComponentClass('Shunt')] p1: gap=0 collisioncheckmode=3 verticalgap=0 showdistances=FALSE
ComponentClearance ComponentClearance_MountingHoles_FiducialMarks [InComponentClass('Mounting Holes') vs InComponentClass('FiducialMark')] p2: gap=50 collisioncheckmode=3 verticalgap=10 showdistances=FALSE
ComponentClearance ComponentClearance_Logo [InComponentClass('Logo')] p3: gap=0 collisioncheckmode=3 verticalgap=0 showdistances=FALSE
ComponentClearance ComponentClearance_ScrewToNut [(HasFootprint('NY PMS 440 0025 PH')) vs (HasFootprint('Keystone_1902C'))] p4: gap=5 collisioncheckmode=3 verticalgap=10 showdistances=FALSE
ComponentClearance ComponentClearance_MountingHoles [InComponentClass('Mounting Holes')] p5: gap=20 collisioncheckmode=3 verticalgap=100000 showdistances=FALSE
ComponentClearance ComponentClearance_SmallPassives [HasFootprint('0201*') or HasFootprint('0402*') or HasFootprint('0508') or HasFootprint('0603*') or HasFootprint('0612') or HasFootprint('0805*') or HasFootprint('0815*') or HasFootprint('0830*') or HasFootprint('1206*') or HasFootprint('1210*') or HasFootprint('1808*') or HasFootprint('1812*') or HasFootprint('1825*') or HasFootprint('2010*') or HasFootprint('2220*') or HasFootprint('2225*') or HasFootprint('2512*') or HasFootprint('2728*') or HasFootprint('3518*') vs HasFootprint('0201*') or HasFootprint('0402*') or HasFootprint('0508') or HasFootprint('0603*') or HasFootprint('0612') or HasFootprint('0805*') or HasFootprint('0815*') or HasFootprint('0830*') or HasFootprint('1206*') or HasFootprint('1210*') or HasFootprint('1808*') or HasFootprint('1812*') or HasFootprint('1825*') or HasFootprint('2010*') or HasFootprint('2220*') or HasFootprint('2225*') or HasFootprint('2512*') or HasFootprint('2728*') or HasFootprint('3518*')] p6: gap=15 collisioncheckmode=3 verticalgap=10 showdistances=FALSE
ComponentClearance ComponentClearance_THtoSMT [IsThruComponent vs IsSMTComponent] p7: gap=20 collisioncheckmode=3 verticalgap=30 showdistances=FALSE
ComponentClearance ComponentClearance_THtoTH [IsThruComponent vs IsThruComponent] p8: gap=10 collisioncheckmode=3 verticalgap=10 showdistances=FALSE
ComponentClearance [All] p9: gap=15 collisioncheckmode=3 verticalgap=10 showdistances=FALSE
DiffPairsRouting [All] p0 off: scope1count=1 scope1_0_kind=Board scope1_0_value=Board scope2count=1 scope2_0_kind=Board scope2_0_value=Board commentlength=0
DiffPairsRouting 90_DiffPair_DiffPairsRouting [All] p0 off: scope1count=1 scope1_0_kind=Board scope1_0_value=Board scope2count=1 scope2_0_kind=Board scope2_0_value=Board commentlength=137 // Protel DXP Scope 1 Expression Was: InDifferentialPair ('C_USB_T') Or InDifferentialPair ('USB2_RP') Or InDifferentialPair ('C_USB_B')
DiffPairsRouting 100_DiffPair_DiffPairsRouting [All] p0 off: scope1count=1 scope1_0_kind=Board scope1_0_value=Board scope2count=1 scope2_0_kind=Board scope2_0_value=Board commentlength=97 // Protel DXP Scope 1 Expression Was: InDifferentialPair ('C_SBU') Or InDifferentialPair ('AUX')
DiffPairsRouting 100_DiffPair_DiffPairsRouting [InDifferentialPair ('C_SBU') Or InDifferentialPair ('AUX')] p1 off: maxlimit=6.5 minlimit=5 mostfreqgap=6.5 toplayer_maxgap=5.5 toplayer_prefgap=5.5 toplayer_minwidth=15 toplayer_maxwidth=15 toplayer_prefwidth=15 midlayer1_mingap=5.5 midlayer1_minwidth=15 midlayer1_maxwidth=15 midlayer1_prefwidth=15 midlayer2_mingap=5.5 midlayer2_maxgap=5.5 midlayer2_prefgap=5.5 midlayer2_minwidth=15 midlayer2_maxwidth=15 midlayer2_prefwidth=15 bottomlayer_mingap=5.5 bottomlayer_maxgap=5.5 bottomlayer_prefgap=5.5 bottomlayer_minwidth=15 bottomlayer_maxwidth=15 bottomlayer_prefwidth=15 maxuncoupledlength=500
DiffPairsRouting 90_DiffPair_DiffPairsRouting [InDifferentialPair ('C_USB_T') Or InDifferentialPair ('USB2_RP') Or InDifferentialPair ('C_USB_B')] p2 off: maxlimit=5 minlimit=3.5 mostfreqgap=5 toplayer_maxgap=4.75 toplayer_prefgap=4.75 toplayer_minwidth=15 toplayer_maxwidth=15 toplayer_prefwidth=15 midlayer1_mingap=5 midlayer1_minwidth=15 midlayer1_maxwidth=15 midlayer1_prefwidth=15 midlayer2_mingap=5 midlayer2_minwidth=15 midlayer2_maxwidth=15 midlayer2_prefwidth=15 bottomlayer_mingap=5 bottomlayer_minwidth=15 bottomlayer_maxwidth=15 bottomlayer_prefwidth=15 maxuncoupledlength=500
DiffPairsRouting [All] p3 off: maxlimit=100 minlimit=10 mostfreqgap=10 toplayer_minwidth=15 toplayer_maxwidth=15 toplayer_prefwidth=15 midlayer1_minwidth=15 midlayer1_maxwidth=15 midlayer1_prefwidth=15 midlayer2_minwidth=15 midlayer2_maxwidth=15 midlayer2_prefwidth=15 bottomlayer_minwidth=15 bottomlayer_maxwidth=15 bottomlayer_prefwidth=15 maxuncoupledlength=1000
FabricationTestPointUsage TestPointUsage [All] p0: scope1count=1 scope1_0_kind=Board scope1_0_value=Board scope2count=1 scope2_0_kind=Board scope2_0_value=Board commentlength=0 valid=2 allowmultiple=FALSE
FabricationTestPointUsage TestPointUsage [All] p1: valid=2 allowmultiple=FALSE
FabricationTestpoint Testpoint [All] p0: scope1count=1 scope1_0_kind=Board scope1_0_value=Board scope2count=1 scope2_0_kind=Board scope2_0_value=Board commentlength=0 side=3 testpointundercomponent=TRUE minsize=40 maxsize=100 preferedsize=60 minholesize=0 maxholesize=40 preferedholesize=32 testpointgrid=1
FabricationTestpoint Testpoint [All] p1: side=3 testpointundercomponent=TRUE minsize=40 maxsize=100 preferedsize=60 minholesize=0 maxholesize=40 preferedholesize=32 testpointgrid=1 allowsidetop=TRUE allowsidebottom=TRUE usegrid=TRUE gridtolerance=0.01
FanoutControl Fanout_LCC [All] p0 off: scope1count=1 scope1_0_kind=Board scope1_0_value=Board scope2count=1 scope2_0_kind=Board scope2_0_value=Board commentlength=69 // Protel DXP Scope 1 Expression Was: IsLCC   Fanout_LCC (Default Rule)
FanoutControl Fanout_BGA [All] p0 off: scope1count=1 scope1_0_kind=Board scope1_0_value=Board scope2count=1 scope2_0_kind=Board scope2_0_value=Board commentlength=69 // Protel DXP Scope 1 Expression Was: IsBGA   Fanout_BGA (Default Rule)
FanoutControl Fanout_SOIC [All] p0 off: scope1count=1 scope1_0_kind=Board scope1_0_value=Board scope2count=1 scope2_0_kind=Board scope2_0_value=Board commentlength=71 // Protel DXP Scope 1 Expression Was: IsSOIC   Fanout_SOIC (Default Rule)
FanoutControl Fanout_Default [All] p0: scope1count=1 scope1_0_kind=Board scope1_0_value=Board scope2count=1 scope2_0_kind=Board scope2_0_value=Board commentlength=30 // Fanout_Default (Default Rule)
FanoutControl Fanout_Small [All] p0 off: scope1count=1 scope1_0_kind=Board scope1_0_value=Board scope2count=1 scope2_0_kind=Board scope2_0_value=Board commentlength=84 // Protel DXP Scope 1 Expression Was: (CompPinCount < 5)   Fanout_Small (Default Rule)
FanoutControl Fanout_LCC [IsLCC] p1: bgadir=Out bgaviamode=Centered fanoutstyle=Auto fanoutdirection=Alternating viagrid=1 // Fanout_LCC (Default Rule)
FanoutControl Fanout_BGA [IsBGA] p2: bgadir=Out bgaviamode=Centered fanoutstyle=Auto fanoutdirection=Alternating viagrid=1 // Fanout_BGA (Default Rule)
FanoutControl Fanout_Default [All] p4: bgadir=Out bgaviamode=Centered fanoutstyle=Auto fanoutdirection=Alternating viagrid=1 // Fanout_Default (Default Rule)
FanoutControl Fanout_Small [(CompPinCount < 5)] p5: bgadir=Out bgaviamode=Centered fanoutstyle=Auto fanoutdirection=OutThenIn viagrid=1 // Fanout_Small (Default Rule)
Height [All] p0: scope1count=1 scope1_0_kind=Board scope1_0_value=Board scope2count=1 scope2_0_kind=Board scope2_0_value=Board commentlength=0
HoleSize [All] p0: scope1count=1 scope1_0_kind=Board scope1_0_value=Board scope2count=1 scope2_0_kind=Board scope2_0_value=Board commentlength=0 absolutevalues=TRUE maxlimit=251 minlimit=6 maxpercent=80.000 minpercent=20.000
HoleSize [All] p1: absolutevalues=TRUE maxlimit=251 minlimit=6 maxpercent=80.000 minpercent=20.000
HoleToHoleClearance HoleToHoleClearance_Slot [All] p0 off: scope1count=1 scope1_0_kind=Board scope1_0_value=Board scope2count=1 scope2_0_kind=Board scope2_0_value=Board commentlength=50 // Protel DXP Scope 2 Expression Was: HasSlotHole
HoleToHoleClearance [All] p0: scope1count=1 scope1_0_kind=Board scope1_0_value=Board scope2count=1 scope2_0_kind=Board scope2_0_value=Board commentlength=0
HoleToHoleClearance HoleToHoleClearance_Slot [HasSlotHole vs HasSlotHole] p1: gap=0 allowstackedmicrovias=TRUE
HoleToHoleClearance [All] p2: gap=5 allowstackedmicrovias=FALSE
LayerPairs [All] p0: scope1count=1 scope1_0_kind=Board scope1_0_value=Board scope2count=1 scope2_0_kind=Board scope2_0_value=Board commentlength=0 enforce=TRUE
MatchedLengths 90_DiffPair_MatchedLengths [All] p0 off: scope1count=1 scope1_0_kind=Board scope1_0_value=Board scope2count=1 scope2_0_kind=Board scope2_0_value=Board commentlength=137 tolerance=500 amplitude=200 gap=20 style=90-Degree // Protel DXP Scope 1 Expression Was: InDifferentialPair ('C_USB_T') Or InDifferentialPair ('USB2_RP') Or InDifferentialPair ('C_USB_B')
MatchedLengths 100_DiffPair_MatchedLengths [All] p0 off: scope1count=1 scope1_0_kind=Board scope1_0_value=Board scope2count=1 scope2_0_kind=Board scope2_0_value=Board commentlength=97 tolerance=500 amplitude=200 gap=20 style=90-Degree // Protel DXP Scope 1 Expression Was: InDifferentialPair ('C_SBU') Or InDifferentialPair ('AUX')
MatchedLengths 100_DiffPair_MatchedLengths [InDifferentialPair ('C_SBU') Or InDifferentialPair ('AUX')] p1: tolerance=500 checknetsindiffpair=TRUE checkdiffpairvsdiffpair=FALSE checkothers=FALSE
MatchedLengths 90_DiffPair_MatchedLengths [InDifferentialPair ('C_USB_T') Or InDifferentialPair ('USB2_RP') Or InDifferentialPair ('C_USB_B')] p2: tolerance=500 checknetsindiffpair=TRUE checkdiffpairvsdiffpair=FALSE checkothers=FALSE
MinimumAnnularRing MinimumAnnularRing_ThermalPadVias [All] p0 off: scope1count=1 scope1_0_kind=Board scope1_0_value=Board scope2count=1 scope2_0_kind=Board scope2_0_value=Board commentlength=63 minimumring=5.91 // Protel DXP Scope 1 Expression Was: IsVia and InAnyComponent
MinimumAnnularRing [All] p0: scope1count=1 scope1_0_kind=Board scope1_0_value=Board scope2count=1 scope2_0_kind=Board scope2_0_value=Board commentlength=0 minimumring=3
MinimumAnnularRing MinimumAnnularRing_ThermalPadVias [IsVia and InAnyComponent] p1: minimumring=5.91
MinimumAnnularRing [All] p2: minimumring=3
MinimumSolderMaskSliver MinimumSolderMaskSliver_Logo [All] p0: scope1count=1 scope1_0_kind=ComponentClass scope1_0_value=Logo scope2count=1 scope2_0_kind=ComponentClass scope2_0_value=Logo commentlength=0
MinimumSolderMaskSliver [All] p0: scope1count=1 scope1_0_kind=Board scope1_0_value=Board scope2count=1 scope2_0_kind=Board scope2_0_value=Board commentlength=0
MinimumSolderMaskSliver MinimumSolderMaskSliver_Logo [InComponentClass('Logo') vs InComponentClass('Logo')] p1: minsoldermaskwidth=0.7
MinimumSolderMaskSliver [All] p2: minsoldermaskwidth=3
NetAntennae [All] p0: scope1count=1 scope1_0_kind=Board scope1_0_value=Board scope2count=1 scope2_0_kind=Board scope2_0_value=Board commentlength=0
PasteMaskExpansion [All] p0: scope1count=1 scope1_0_kind=Board scope1_0_value=Board scope2count=1 scope2_0_kind=Board scope2_0_value=Board commentlength=0 expansion=0
PlaneClearance [All] p0: scope1count=1 scope1_0_kind=Board scope1_0_value=Board scope2count=1 scope2_0_kind=Board scope2_0_value=Board commentlength=0 clearance=8
PlaneClearance [All] p1: clearance=8
PlaneConnect [All] p0: scope1count=1 scope1_0_kind=Board scope1_0_value=Board scope2count=1 scope2_0_kind=Board scope2_0_value=Board commentlength=0 planeconnectstyle=Direct reliefexpansion=10 reliefentries=4 reliefconductorwidth=12 reliefairgap=4
PlaneConnect [All] p1: planeconnectstyle=Direct reliefexpansion=10 reliefentries=4 reliefconductorwidth=12 reliefairgap=4
PolygonConnect [All] p0: scope1count=1 scope1_0_kind=Board scope1_0_value=Board scope2count=1 scope2_0_kind=Board scope2_0_value=Board commentlength=0 connectstyle=Direct reliefconductorwidth=10 reliefentries=4 polygonreliefangle="90 Angle"
PolygonConnect [All] p1: connectstyle=Direct reliefconductorwidth=10 reliefentries=4 polygonreliefangle="90 Angle" airgapwidth=10
RoutingCorners [All] p0: scope1count=1 scope1_0_kind=Board scope1_0_value=Board scope2count=1 scope2_0_kind=Board scope2_0_value=Board commentlength=0 cornerstyle=45-Degree minsetback=100 maxsetback=100
RoutingLayers [All] p0: scope1count=1 scope1_0_kind=Board scope1_0_value=Board scope2count=1 scope2_0_kind=Board scope2_0_value=Board commentlength=0 top layer=Automatic mid layer 1=Automatic mid layer 2=Automatic bottom layer=Automatic
RoutingPriority [All] p0: scope1count=1 scope1_0_kind=Board scope1_0_value=Board scope2count=1 scope2_0_kind=Board scope2_0_value=Board commentlength=0
RoutingTopology [All] p0: scope1count=1 scope1_0_kind=Board scope1_0_value=Board scope2count=1 scope2_0_kind=Board scope2_0_value=Board commentlength=0 topology=Shortest
RoutingVias ThermalPadVias [All] p0 off: scope1count=1 scope1_0_kind=Board scope1_0_value=Board scope2count=1 scope2_0_kind=Board scope2_0_value=Board commentlength=63 holewidth=7.87 width=19.68 viastyle="Through Hole" minholewidth=6 minwidth=12 maxholewidth=12.99 maxwidth=23.62 // Protel DXP Scope 1 Expression Was: IsVia and InAnyComponent
RoutingVias [All] p0: scope1count=1 scope1_0_kind=Board scope1_0_value=Board scope2count=1 scope2_0_kind=Board scope2_0_value=Board commentlength=0 holewidth=16 width=34 viastyle="Through Hole" minholewidth=6 minwidth=12 maxholewidth=12 maxwidth=65
RoutingVias ThermalPadVias [IsVia and InAnyComponent] p1: holewidth=7.87 width=19.68 viastyle="Through Hole" minholewidth=6 minwidth=12 maxholewidth=12.99 maxwidth=23.62
RoutingVias [All] p2: holewidth=16 width=34 viastyle="Through Hole" minholewidth=6 minwidth=12 maxholewidth=12 maxwidth=65
SMDToCorner [All] p0 off: scope1count=1 scope1_0_kind=Board scope1_0_value=Board scope2count=1 scope2_0_kind=Board scope2_0_value=Board commentlength=0 distance=5000
SMDToCorner [All] p1 off: distance=5000
ShortCircuit [All] p0: scope1count=1 scope1_0_kind=Board scope1_0_value=Board scope2count=1 scope2_0_kind=Board scope2_0_value=Board commentlength=0 allowed=FALSE
SilkToBoardRegionClearance [All] p0: scope1count=1 scope1_0_kind=Board scope1_0_value=Board scope2count=1 scope2_0_kind=Board scope2_0_value=Board commentlength=0
SilkToSilkClearance SilkToSilkClearance_Pb-FreeLogo [All] p0 off: scope1count=1 scope1_0_kind=Board scope1_0_value=Board scope2count=1 scope2_0_kind=Board scope2_0_value=Board commentlength=120 // Protel DXP Scope 2 Expression Was: (HasFootprint('Pb-Free_Overlay_Medium') OR HasFootprint('Pb-Free_Overlay_Small'))
SilkToSilkClearance [All] p0: scope1count=1 scope1_0_kind=Board scope1_0_value=Board scope2count=1 scope2_0_kind=Board scope2_0_value=Board commentlength=0
SilkToSilkClearance SilkToSilkClearance_Pb-FreeLogo [(HasFootprint('Pb-Free_Overlay_Medium') OR HasFootprint('Pb-Free_Overlay_Small')) vs (HasFootprint('Pb-Free_Overlay_Medium') OR HasFootprint('Pb-Free_Overlay_Small'))] p1: silktosilkclearance=0
SilkToSilkClearance [All] p2: silktosilkclearance=0.25
SilkToSolderMaskClearance SilkscreenOverComponentPads [All] p0 off: scope1count=1 scope1_0_kind=Board scope1_0_value=Board scope2count=1 scope2_0_kind=Board scope2_0_value=Board commentlength=44 // Protel DXP Scope 1 Expression Was: IsPad
SilkToSolderMaskClearance SilkscreenOverComponentPads [IsPad] p1: minsilkscreentomaskgap=1 clearancetoexposedcopper=TRUE
SolderMaskExpansion [All] p0: scope1count=1 scope1_0_kind=Board scope1_0_value=Board scope2count=1 scope2_0_kind=Board scope2_0_value=Board commentlength=0 expansion=1.97
SolderMaskExpansion [All] p1: expansion=1.97
UnRoutedNet [All] p0: scope1count=1 scope1_0_kind=Board scope1_0_value=Board scope2count=1 scope2_0_kind=Board scope2_0_value=Board commentlength=0
UnpouredPolygon [All] p0: scope1count=1 scope1_0_kind=Board scope1_0_value=Board scope2count=1 scope2_0_kind=Board scope2_0_value=Board commentlength=0
UnpouredPolygon [All] p1: allowunpoured=FALSE
Width [All] p0: scope1count=1 scope1_0_kind=Board scope1_0_value=Board scope2count=1 scope2_0_kind=Board scope2_0_value=Board commentlength=0 maxlimit=100 minlimit=4 preferedwidth=10
Width 90_DiffPair_Width [All] p0 off: scope1count=1 scope1_0_kind=Board scope1_0_value=Board scope2count=1 scope2_0_kind=Board scope2_0_value=Board commentlength=134 maxlimit=5.8 minlimit=4 preferedwidth=5.8 // Protel DXP Scope 1 Expression Was: InDifferentialPair('C_USB_T') Or InDifferentialPair('USB2_RP') Or InDifferentialPair('C_USB_B')
Width 100_DiffPair_Width [All] p0 off: scope1count=1 scope1_0_kind=Board scope1_0_value=Board scope2count=1 scope2_0_kind=Board scope2_0_value=Board commentlength=95 maxlimit=5 minlimit=4 preferedwidth=4.4 // Protel DXP Scope 1 Expression Was: InDifferentialPair('C_SBU') Or InDifferentialPair('AUX')
Width 100_DiffPair_Width [InDifferentialPair('C_SBU') Or InDifferentialPair('AUX')] p1: maxlimit=5 minlimit=4 preferedwidth=4.4 toplayer_prefwidth=5 midlayer1_maxwidth=4.4 minimp=50.000000 maximp=50.000000 favimp=50.000000
Width 90_DiffPair_Width [InDifferentialPair('C_USB_T') Or InDifferentialPair('USB2_RP') Or InDifferentialPair('C_USB_B')] p2: maxlimit=5.8 minlimit=4 preferedwidth=5.8 midlayer1_maxwidth=4.8 midlayer1_prefwidth=4.8 midlayer2_maxwidth=4.8 midlayer2_prefwidth=4.8 minimp=50.000000 maximp=50.000000 favimp=50.000000
Width [All] p3: maxlimit=100 minlimit=4 preferedwidth=10 checkconnectedcopper=TRUE
13 further rules are at their usual default settings.

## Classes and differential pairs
component class Header: J6 J7
component class AssemblyNote: ZZ2 ZZ3 ZZ4
component class FiducialMark: FID1 FID2 FID3 FID4 FID5 FID6
component class HVL117D_Hardware_ANSI-B: FID1 FID2 FID3 FID4 FID5 FID6 H1 H2 H3 H4 H5 H6 H7 H8 Logo1 Logo2 Logo3 ZZ2 ZZ3 ZZ4
component class Logo: Logo1
component class "Mounting Holes": H1 H2 H3 H4
component class HVL117D_Power_Delivery: C1 C2 C3 C4 C5 C6 C7 C8 C9 C10 C11 C12 C13 C14 C15 C16 C17 C18 C19 C53 D1 D2 D3 D4 D5 D6 D7 D8 D9 J1 J2 J3 J6 L1 Q1 Q2 Q3 Q4 Q5 Q6 Q7 Q8 Q9 Q10 R1 R2 R3 R4 R5 R6 R7 R8 R9 R10 R11 R12 R13 R14 R15 R16 R17 R18 R19 R20 R21 R22 R23 R24 R25 R26 R28 R29 R30 R31 R32 R33 R34 R35 R36 R37 R38 R39 R40 R41 R42 R43 R44 R45 R46 R47 R48 R49 R50 R51 R52 R53 R54 R55 R56 R57 R58 R59 R60 R61 R62 R63 R64 R65 R66 R67 R68 R69 R70 R71 R72 R73 R74 R75 R76 R77 R78 R79 R80 R86 R87 R89 R90 R96 S1 S2 TP1 TP2 TP3 TP4 U1 U2 U3 U4
component class HVL117D_Power_Path: C20 C22 C23 C24 C25 C26 C27 C28 C29 C30 C31 C33 C34 C35 C36 C37 C38 C39 C40 C41 C42 C44 C45 C46 C47 C48 C49 C50 C51 C52 J4 J5 J7 L2 L3 L4 R27 R81 R82 R83 R84 R85 R88 R91 R92 R93 R94 R95 R97 R101 R102 R103 R104 R108 R109 S3 TP5 U5 U6 U7
differential pair AUX: +AUX_P -AUX_N
differential pair C_SBU: +C_SBU_P -C_SBU_N
differential pair C_USB_B: +C_USB_B_P -C_USB_B_N
differential pair C_USB_T: +C_USB_T_P -C_USB_T_N
differential pair " ": +USB2_RP_P -USB2_RP_N

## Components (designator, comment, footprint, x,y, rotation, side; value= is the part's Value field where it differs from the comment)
C1 "GRM188R61E106MA73" 0603 748,430 r270 bottom
C2 "CL03A104KP3NNNC" 0201#1 1287,1004 r90 bottom
C3 "GRM033R60J224ME90" 0201#1 1036,928.37 r90 bottom
C4 "GRM188R61E106MA73" 0603 990,1011.37 r270 bottom
C5 "C1005X7R1H104M" 0402 1056,1064.37 r270 bottom
C6 "C1005JB1V105K050BC" 0402 1107,854.37 r180 bottom
C7 "GRM155R71H103KA88D" 0402 888,361 r180 bottom
C8 "GRM155R71H103KA88D" 0402 888,402 r180 bottom
C9 "GRM155R71H103KA88D" 0402 1119,360 r0 bottom
C10 "GRM155R71H103KA88D" 0402 1119,401 r0 bottom
C11 "GRM188R61A226ME15D" 0603_100 1124,966.37 r180 bottom
C12 "CL03A104KP3NNNC" 0201#1 1115,1069.37 r180 bottom
C13 "CL03A105MP3NSNC" 0201#1 903,1029 r0 bottom
C14 "CL05A106MP5NUNC" 0402 886,930.37 r0 bottom
C15 "GRM033R71E221KA01D" 0201#2 1125.01,761 r180 top
C16 "CL03A105MP3NSNC" 0201#1 903,1058 r0 bottom
C17 "CL03A105MP3NSNC" 0201#1 901,855 r0 bottom
C18 "CL03A105MP3NSNC" 0201#1 903,1000.37 r0 bottom
C19 "GRM033R71E221KA01D" 0201#1 1192,761 r0 top
C20 "C1005X7R1H104M" 0402 468,585 r270 bottom
C22 "C2012X5R1E106K125AB" 0805_HV 386,704 r270 bottom
C23 "C1005X7R1H104M" 0402 367,826 r90 bottom
C24 "C2012X5R1V226M125AC" 0805_HV 658,747 r180 bottom
C25 "C2012X5R1V226M125AC" 0805_HV 658,666 r180 bottom
C26 "C1005X7R1H104M" 0402 674,606 r180 bottom
C27 "GRM1555C1H121JA01D" 0402 674,524 r180 bottom
C28 "C1005C0G1H331J" 0402 516,563 r270 bottom
C29 "GRM155R71H562KA88D" 0402 536,494 r180 bottom
C30 "GRM1555C1H121JA01D" 0402 406,582 r90 bottom
C31 "C1005X7R1H104M" 0402 1322,1471 r90 bottom
C33 "C2012X5R1E106K125AB" 0805_HV 1279.6,1337 r270 bottom
C34 "C1005X7R1H104M" 0402 1340,1343.7 r270 bottom
C35 "C2012X5R1V226M125AC" 0805_HV 1620.6,1341 r180 bottom
C36 "C2012X5R1V226M125AC" 0805_HV 1620.6,1256 r180 bottom
C37 "C1005X7R1H104M" 0402 1713,1576 r270 bottom
C38 "GRM1555C1H121JA01D" 0402 1626.6,1141 r180 bottom
C39 "CC0402KRX7R9BB101" 0402 1456.6,1157 r270 bottom
C40 "GRM155R61H222KA01D" 0402 1416,1157 r90 bottom
C41 "GRM1555C1H121JA01D" 0402 1286.6,1237 r180 bottom
C42 "C1005X7R1H104M" 0402 402.12,1522.69 r180 bottom
C44 "C2012X5R1E106K125AB" 0805_HV 543.12,1587.69 r180 bottom
C45 "C1005X7R1H104M" 0402 581,1675 r90 bottom
C46 "C2012X5R1V226M125AC" 0805_HV 575,1323 r90 bottom
C47 "C2012X5R1V226M125AC" 0805_HV 495,1323 r90 bottom
C48 "C1005X7R1H104M" 0402 568,1189 r180 bottom
C49 "GRM1555C1H121JA01D" 0402 392.12,1275.91 r90 bottom
C50 "GRM1555C1H910JA01D" 0402 358.12,1467.69 r180 bottom
C51 "GRM155R71H182KA01D" 0402 357.12,1385.69 r180 bottom
C52 "GRM1555C1H121JA01D" 0402 389.12,1591.69 r90 bottom
C53 "GRM033R61A103KA01D" 0201#1 1385,1511 r270 top
D1 "B340A-13-F" SMA 1276,467 r270 bottom
D2 "LW QH8G-Q2S2-3K5L-1" "LW QH8G_White" 450,100 r270 top
D3 "LW QH8G-Q2S2-3K5L-1" "LW QH8G_White" 650,100 r270 top
D4 "LW QH8G-Q2S2-3K5L-1" "LW QH8G_White" 450,300 r270 top
D5 "LW QH8G-Q2S2-3K5L-1" "LW QH8G_White" 650,300 r270 top
D6 "LW QH8G-Q2S2-3K5L-1" "LW QH8G_White" 1550,100 r270 top
D7 "LW QH8G-Q2S2-3K5L-1" "LW QH8G_White" 1350,100 r270 top
D8 "LW QH8G-Q2S2-3K5L-1" "LW QH8G_White" 1350,300 r270 top
D9 "LW QH8G-Q2S2-3K5L-1" "LW QH8G_White" 1550,300 r270 top
FID1 "Fiducial" Fiducial10-20 375,1450 r0 top
FID2 "Fiducial" Fiducial10-20 1158,1450 r0 top
FID3 "Fiducial" Fiducial10-20 375,450 r0 top
FID4 "Fiducial" Fiducial10-20 150,1600 r180 bottom
FID5 "Fiducial" Fiducial10-20 1475,470 r180 bottom
FID6 "Fiducial" Fiducial10-20 150,470 r180 bottom
H1 "NY PMS 440 0025 PH" "NY PMS 440 0025 PH" 1825,1825 r0 top locked
H2 "NY PMS 440 0025 PH" "NY PMS 440 0025 PH" 175,1825 r0 top locked
H3 "NY PMS 440 0025 PH" "NY PMS 440 0025 PH" 175,175 r0 top locked
H4 "NY PMS 440 0025 PH" "NY PMS 440 0025 PH" 1825,175 r0 top locked
H5 "1902C" Keystone_1902C 1825,1825 r180 bottom locked
H6 "1902C" Keystone_1902C 175,1825 r180 bottom locked
H7 "1902C" Keystone_1902C 175,175 r180 bottom locked
H8 "1902C" Keystone_1902C 1825,175 r180 bottom locked
J1 "20-0000016-01" Lintes_20-0000016-01 999,10 r0 top
J2 "PPPC102LFBN-RC" Sullins_PPPC102LFBN-RC 149,1000 r90 top
J3 "PPPC102LFBN-RC" Sullins_PPPC102LFBN-RC 1850,1000 r90 top
J4 "JPD1135-509-7F" CONN_JPD1135-509 1000,2000 r180 top
J5 "PPPC031LFBN-RC" Sullins_PPPC031LFBN-RC 1799,401 r180 top
J6 "90120-0122" CONN_90120-0122 550,418 r0 top
J7 "15-91-2040" Molex_15-91-2040 551,1616 r90 top
L1 "FBMJ2125HM210NT" 0805_HV 1230,735 r270 bottom
L2 "ASPI-0630LR-100M-T15" ASPI-0630LR 562,943 r0 bottom
L3 "ASPI-0630LR-100M-T15" ASPI-0630LR 1518,1549 r0 bottom
L4 "ASPI-0630LR-100M-T15" ASPI-0630LR 771,1294 r270 bottom
Logo1 "Texas Instruments" TI_Stacked_Overlay_Small 851,687 r0 top
Logo2 "Pb-Free Symbol" Pb-Free_Overlay_Small 1850,1589 r0 top
Logo3 "FCC disclaimer" FCC_disclaimer_stacked 2036,1639 r0 top
Q1 "CSD17309Q3" TRANS_NexFET_Q3 935,739 r0 bottom
Q2 "CSD17309Q3" TRANS_NexFET_Q3 1100,739 r180 bottom
Q3 "DTC114EUAT106" SOT-323 482,100 r0 bottom
Q4 "DTC114EUAT106" SOT-323 619,100 r180 bottom
Q5 "DTC114EUAT106" SOT-323 482,300 r0 bottom
Q6 "DTC114EUAT106" SOT-323 618,300 r180 bottom
Q7 "DTC114EUAT106" SOT-323 1518,100 r180 bottom
Q8 "DTC114EUAT106" SOT-323 1382,100 r0 bottom
Q9 "DTC114EUAT106" SOT-323 1382,300 r0 bottom
Q10 "DTC114EUAT106" SOT-323 1518,300 r180 bottom
R1 "WSL0805R0100FEA18" 0805_HV 840,568 r90 bottom
R2 "ERJ-1GE0R00C" 0201M 765,527.5 r0 bottom
R3 "ERJ-1GE0R00C" 0201M 765,562.5 r0 bottom
R4 "CRCW04023K30JNED" 0402 1624,1004 r270 bottom
R5 "ERJ-1GE0R00C" 0201M 915,528 r180 bottom
R6 "ERJ-1GE0R00C" 0201M 915,563 r180 bottom
R7 "CRCW04023K30JNED" 0402 1682,962 r270 bottom
R8 "CRCW04023K30JNED" 0402 1283,925 r270 bottom
R9 "CRCW04023K30JNED" 0402 1682,867 r270 bottom
R10 "ERJ-1GE0R00C" 0201M 1125.01,789 r0 top
R11 "ERJ-1GE0R00C" 0201M 1192,789 r180 top
R12 "CRCW02011K00FKED" 0201M 565,1899 r180 bottom
R13 "CRCW02011K00FKED" 0201M 565,1849 r180 bottom
R14 "CRCW02011K00FKED" 0201M 565,1799 r180 bottom
R15 "CRCW02011K00FKED" 0201M 565,1749 r180 bottom
R16 "ERJ-1GE0R00C" 0201M 308,1251 r180 top
R17 "ERJ-1GE0R00C" 0201M 308,1150 r180 top
R18 "ERJ-1GE0R00C" 0201M 308,1400 r180 top
R19 "ERJ-1GE0R00C" 0201M 308,1299 r180 top
R20 "CRCW02013K83FKED" 0201M 377,650 r0 top
R21 "CRCW0201100KFKED" 0201M 406,1749 r0 bottom
R22 "ERJ-1GE0R00C" 0201M 1078,774 r270 top
R23 "ERJ-1GE0R00C" 0201M 308,1199 r0 top
R24 "CRCW0201100KFKED" 0201M 378,550 r0 top
R25 "CRCW0201100KFKED" 0201M 406,1799 r0 bottom
R26 "CRCW0201100KFKED" 0201M 1355,1508 r90 top
R27 "CRCW02011K00FKED" 0201M 1612,1524 r0 top
R28 "CRCW040215K0FKED" 0402 886,891 r180 bottom
R29 "CRCW0201100KFKED" 0201M 406,1849 r0 bottom
R30 "ERJ-1GE0R00C" 0201M 1244,774 r270 top
R31 "ERJ-1GE0R00C" 0201M 308,1100 r0 top
R32 "ERJ-1GE0R00C" 0201M 308,1049 r180 top
R33 "CRCW0201100KFKED" 0201M 406,1899 r0 bottom
R34 "ERJ-1GE0R00C" 0201M 308,999 r0 top
R35 "ERJ-1GE0R00C" 0201M 308,850 r180 top
R36 "ERJ-1GE0R00C" 0201M 308,950 r180 top
R37 "ERJ-1GE0R00C" 0201M 308,750 r180 top
R38 "ERJ-1GE0R00C" 0201M 308,900 r0 top
R39 "ERJ-1GE0R00C" 0201M 308,650 r180 top
R40 "ERJ-1GE0R00C" 0201M 308,700 r0 top
R41 "ERJ-1GE0R00C" 0201M 308,550 r180 top
R42 "CRCW02011K00FKED" 0201M 1590,1900 r180 bottom
R43 "CRCW02011K00FKED" 0201M 1590,1850 r180 bottom
R44 "CRCW02011K00FKED" 0201M 1590,1800 r180 bottom
R45 "CRCW02011K00FKED" 0201M 1590,1750 r180 bottom
R46 "ERJ-1GE0R00C" 0201M 1692,1450 r180 top
R47 "ERJ-1GE0R00C" 0201M 1692,1350 r180 top
R48 "ERJ-1GE0R00C" 0201M 1692,1400 r180 top
R49 "CRCW0201100KFKED" 0201M 1400,1800 r0 bottom
R50 "ERJ-1GE0R00C" 0201M 1692,1250 r180 top
R51 "ERJ-1GE0R00C" 0201M 1692,1300 r0 top
R52 "CRCW0201100KFKED" 0201M 1400,1850 r0 bottom
R53 "ERJ-1GE0R00C" 0201M 1692,1150 r0 top
R54 "ERJ-1GE0R00C" 0201M 1692,1200 r0 top
R55 "CRCW0201100KFKED" 0201M 1400,1901 r0 bottom
R56 "ERJ-1GE0R00C" 0201M 900,969.37 r180 bottom
R57 "ERJ-1GE0R00C" 0201M 1692,1050 r0 top
R58 "ERJ-1GE0R00C" 0201M 1692,1100 r0 top
R59 "ERJ-1GE0R00C" 0201M 1692,950 r0 top
R60 "ERJ-1GE0R00C" 0201M 1692,1000 r0 top
R61 "ERJ-1GE0R00C" 0201M 1692,850 r0 top
R62 "ERJ-1GE0R00C" 0201M 1692,900 r0 top
R63 "ERJ-1GE0R00C" 0201M 1692,750 r0 top
R64 "ERJ-1GE0R00C" 0201M 1692,800 r0 top
R65 "ERJ-1GE0R00C" 0201M 1692,650 r0 top
R66 "ERJ-1GE0R00C" 0201M 1692,700 r180 top
R67 "ERJ-1GE0R00C" 0201M 1692,550 r180 top
R68 "ERJ-1GE0R00C" 0201M 1692,600 r180 top
R69 "ERJ-1GE0R00C" 0201M 308,599 r0 top
R70 "CRCW0201100KFKED" 0201M 1370,1459 r0 top
R71 "ERJ-1GE0R00C" 0201M 308,499 r0 top
R72 "CRCW0402560RJNED" 0402 490,100 r270 top
R73 "CRCW0402560RJNED" 0402 610,100 r270 top
R74 "CRCW0402560RJNED" 0402 490,300 r270 top
R75 "CRCW02013K83FKED" 0201M 368,1049 r0 top
R76 "CRCW02013K83FKED" 0201M 369,1150 r0 top
R77 "CRCW02019K09FKED" 0201M 369,1251 r0 top
R78 "CRCW02019K09FKED" 0201M 161,404.96 r270 top
R79 "CRCW02013K83FKED" 0201M 195,404.96 r270 top
R80 "CRCW02013K83FKED" 0201M 229,404.96 r270 top
R81 "CRCW0402220KJNED" 0402 325,711 r90 bottom
R82 "CRCW0402100KFKED" 0402 674,565 r0 bottom
R83 "CRCW040243K2FKED" 0402 324,610 r90 bottom
R84 "CRCW040232K4FKED" 0402 605,576 r270 bottom
R85 "CRCW04022K74FKED" 0402 557,563 r90 bottom
R86 "CRCW0402560RJNED" 0402 610,300 r270 top
R87 "CRCW0402560RJNED" 0402 1510,100 r270 top
R88 "CRCW040247K5FKED" 0402 365,582 r270 bottom
R89 "CRCW0402560RJNED" 0402 1390,100 r270 top
R90 "CRCW0402560RJNED" 0402 1390,300 r270 top
R91 "CRCW0402220KJNED" 0402 1219,1349 r90 bottom
R92 "CRCW0402100KFKED" 0402 1626.6,1186 r0 bottom
R93 "CRCW040243K2FKED" 0402 1219,1253 r90 bottom
R94 "CRCW040219K1FKED" 0402 1552.6,1161 r270 bottom
R95 "CRCW04028K45FKED" 0402 1497.6,1157 r90 bottom
R96 "CRCW0402560RJNED" 0402 1510,300 r270 top
R97 "CRCW040247K5FKED" 0402 1286.6,1196 r0 bottom
R101 "CRCW0402220KJNED" 0402 512.12,1663.69 r0 bottom
R102 "CRCW0402100KFKED" 0402 434.12,1275.91 r270 bottom
R103 "CRCW040243K2FKED" 0402 416.12,1663.69 r0 bottom
R104 "CRCW04027K15FKED" 0402 434.12,1371.91 r270 bottom
R108 "CRCW04029K53FKED" 0402 357.12,1426.69 r0 bottom
R109 "CRCW040247K5FKED" 0402 430.12,1591.69 r270 bottom
S1 "TDA04H0SB1" SW_TDA04H0SB1 550,1856 r0 top
S2 "TDA04H0SB1" SW_TDA04H0SB1 1450,1856 r0 top
S3 "B3U-1000P" SW_B3U-1000P 1491,1524 r0 top
TP1 "TESTPOINT" Keystone_5019 1558,562 r90 top
TP2 "TESTPOINT" Keystone_5019 1362,562 r90 top
TP3 "TESTPOINT" Keystone_5019 1460,817 r0 top
TP4 "TESTPOINT" Keystone_5019 1000,512 r0 top
TP5 "TESTPOINT" Keystone_5019 565,1036 r0 top
U1 "W25Q80DVSNIG" SOIC-8 1452,914 r180 bottom
U2 "TPS65982AAZQZR" ZQZ0096A_Oval 1000,949.37 r0 top
U3 "TPD4E05U06DQA" DQA0010A 800,512.37 r270 top
U4 "TPD4E05U06DQA" DQA0010A 1200,512.37 r270 top
U5 "TPS54335DRCR" DRC0010J 506,706 r270 bottom
U6 "TPS54335DRCR" DRC0010J 1467.6,1308 r270 bottom
U7 "TPS54335DRCR" DRC0010J 530.12,1472.69 r180 bottom
ZZ2 "These assemblies are ESD sensitive, ESD precautions shall be observed." AssemblyNote 185,3829.11 r0 top
ZZ3 "These assemblies must be clean and free from flux and all contaminants. Use of no clean flux is not acceptable." AssemblyNote 185,3740.56 r0 top
ZZ4 "These assemblies must comply with workmanship standards IPC-A-610 Class 2, unless otherwise specified." AssemblyNote 185,3652 r0 top

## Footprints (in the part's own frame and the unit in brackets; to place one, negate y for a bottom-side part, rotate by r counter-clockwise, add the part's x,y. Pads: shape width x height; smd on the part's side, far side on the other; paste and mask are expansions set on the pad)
0201#1 [mm] "Data from Kemet datasheet CC101_COM dated 7/28/11"
  rect 0.46x0.42 smd mask+0.048: 1(-0.33,0) 2(0.33,0)
0201#2 [mm] "Data from Kemet datasheet CC101_COM dated 7/28/11"
  rect 0.46x0.42 smd mask+0: 1(-0.33,0) 2(0.33,0)
0201M [mm] "Data from Kemet datasheet CC101_COM dated 7/28/11"
  rect 0.56x0.52 smd mask+0.048: 1(-0.38,0) 2(0.38,0)
0402 [mm] "0402 from SM-752 data"
  rect 0.8x0.6 smd: 1(-0.6,0) 2(0.6,0)
  silkscreen extent -1.22,-0.52 1.22,0.52
0603 [mm] "0603 from SM-752 data"
  rect 1x0.95 smd: 1(-0.8,0) 2(0.8,0)
  silkscreen extent -1.52,-0.69 1.52,0.69
0603_100 [mm] "SMD, 2-Leads, Body 1.6x0.8mm"
  rect 1x0.95 smd: 1(-0.8,0) 2(0.8,0)
  silkscreen extent -1.52,-0.69 1.52,0.69
0805_HV [mil] "0805 with 30mil clearance between pads"
  rect 50x63 smd: 1(-40,0) 2(40,0)
  silkscreen extent -74,-40 74,40
ASPI-0630LR [mm] "SMD, 2-Leads, Body 7.2x6.65mm"
  rect 2.35x3.4 smd: 1(-3.025,0) 2(3.025,0)
  silkscreen extent -3.75,-3.42 3.75,3.42
AssemblyNote [mil] "Assembly Note"
CONN_90120-0122 [mm] "Molex"
  rect 1.65x1.65 hole 1.016 mask+0: 1(-1.27,0)
  round 1.65 hole 1.016 mask+0: 2(1.27,0)
  silkscreen extent -3.56,-1.27 2.54,1.27
CONN_JPD1135-509 [mm] "Foxconn recommended land pattern"
  round 1.524 hole 1: 1(0,11.95)
  round 2.3 hole 1.6: 2(-2.8,11.95) 3(2.8,11.95) 4(0,9) 5(0,5.25)
  round 2 hole 1.3: 6(-4.75,9) 7(4.75,9)
  round 2.4 hole 1.7: 8(-4.75,2.75) 9(4.75,2.75)
  round 0 hole 1.3 unplated: 10(-1.75,2.75) 11(1.75,2.75)
  silkscreen extent -5.1,0.05 5.1,12.35
DQA0010A [mm] "SON, 10-Leads, Body 1x2.5mm, Pitch 0.5mm, TI Recommended"
  rect 0.55x0.2 smd: 1(-0.425,1) 2(-0.425,0.5) 4(-0.425,-0.5) 5(-0.425,-1) 6(0.425,-1) 7(0.425,-0.5) 9(0.425,0.5) 10(0.425,1)
  rect 0.55x0.4 smd: 3(-0.425,0) 8(0.425,0)
  silkscreen extent -1,-1.45 0.55,1.5
DRC0010J [mm] "SON, 10-Leads, Body 3x3mm, Pitch 0.5mm, Thermal Pad 2.4x1.65mm, TI Recommended"
  oval 0.6x0.24 smd: 1(-1.4,1) 2(-1.4,0.5) 3(-1.4,0) 4(-1.4,-0.5) 5(-1.4,-1) 6(1.4,-1) 7(1.4,-0.5) 8(1.4,0) 9(1.4,0.5) 10(1.4,1)
  rect 1.65x2.4 smd paste-0.825: 11(0,0)
  Top Layer region: 0.135,1.5 0.365,1.5 0.365,1.1 0.135,1.1
  Top Layer region: -0.135,1.1 -0.365,1.1 -0.365,1.5 -0.135,1.5
  Top Layer region: -0.135,-1.5 -0.365,-1.5 -0.365,-1.1 -0.135,-1.1
  Top Layer region: 0.135,-1.1 0.365,-1.1 0.365,-1.5 0.135,-1.5
  silkscreen extent -1.7,-1.7 1.7,1.7
FCC_disclaimer_stacked [mil]
Fiducial10-20 [mm]
  round 1 smd mask+0.5: 1(0,0)
Keystone_1902C [mil] "Hex Standoff, 4-40 threaded, nylon"
Keystone_5019 [mm] "Test Point, Miniature, SMT"
  rect 3.8x2.03 smd: 1(0,0)
  silkscreen extent -2.31,-1.42 2.31,1.42
Lintes_20-0000016-01 [mm] "Connector, Receptacle, USB Type C, SMT"
  rect 1.1x0.3 smd: 1(3.05,8.44) 3(-3.05,8.44)
  rect 1x0.3 smd: 2(0.07,8.44)
  rect 0.3x0.95 smd: A1(-2.7,7.525) A12(2.85,7.525)
  rect 0.25x0.95 smd: A2(-2.175,7.525) A3(-1.675,7.525) A4(-1.175,7.525) A5(-0.675,7.525) A6(-0.175,7.525) A7(0.325,7.525) A8(0.825,7.525) A9(1.325,7.525) A10(1.825,7.525) A11(2.325,7.525)
  rect 0.3x0.85 smd: B1(2.7,5.875) B12(-2.85,5.875)
  rect 0.25x0.85 smd: B2(2.175,5.875) B3(1.675,5.875) B4(1.175,5.875) B5(0.675,5.875) B6(0.175,5.875) B7(-0.325,5.875) B8(-0.825,5.875) B9(-1.325,5.875) B10(-1.825,5.875) B11(-2.325,5.875)
  oval 1.1x1.9 hole 0.7 slot 1.5 at 90 deg: H1(4.323,7.05) H3(-4.323,7.05)
  oval 1.65x1.1 hole 0.7 slot 1.45 at 0 deg: H2(3.949,6.65) H4(-3.949,6.65)
  oval 1.1x1.7 hole 0.7 slot 1.3 at 90 deg: H5(5.7,1.45) H7(-5.7,1.45)
  rrect50% 1.1x1.7 all layers, no hole: H6(5.7,2) H8(-5.7,2)
  silkscreen extent -4.77,0.68 4.77,8.58
"LW QH8G_White" [mm] "SMD, 2-Leads, Body 1x0.5mm"
  rect 0.6x0.6 smd paste-0.3: 1(-0.55,0) 2(0.55,0)
  silkscreen extent 1.1,-0.4 1.3,0.4
Molex_15-91-2040 [mil] "Molex"
  rect 50x144.88 smd: 1(-50,-87.5) 2(-50,87.5) 3(50,-87.5) 4(50,87.5)
  silkscreen extent -100,-150 100,100
"NY PMS 440 0025 PH" [mm] "4-40 nylon screw and mounting hole"
  round 8 hole 3.2: 1(0,0)
Pb-Free_Overlay_Small [mil]
  silkscreen extent -46,-46 46,46
SMA [mm] "Molded Diode, 2-Leads, Body 4.3x2.6mm, IPC Medium Density, based on OnSemi component dimensions and land pattern"
  rect 2x2 smd: 1(-2,0) 2(2,0)
  silkscreen extent -3.66,-1.57 2.79,1.57
SOIC-8 [mm] "duplicate of SO-8.  SOIC, 8-Leads, Body 5.0x4.0mm (max), Pitch 1.27mm, IPC Medium Density"
  oval 2.2x0.6 smd: 1(-2.4,1.905) 2(-2.4,0.635) 3(-2.4,-0.635) 4(-2.4,-1.905) 5(2.4,-1.905) 6(2.4,-0.635) 7(2.4,0.635) 8(2.4,1.905)
  silkscreen extent -0.9,-2.5 0.9,2.5
SOT-323 [mm] "Zetex recommended land pattern.  March 2007"
  rect 0.8x0.6 smd: 1(-0.8,0.65) 2(-0.8,-0.65) 3(0.8,0)
  silkscreen extent -1.14,-1.22 0.77,1.22
Sullins_PPPC031LFBN-RC [mm] "Sullins"
  rect 1.6x1.6 hole 1.016: 1(-2.54,0)
  round 1.6 hole 1.016: 2(0,0) 3(2.54,0)
  silkscreen extent -4.16,-1.37 4.16,1.9
Sullins_PPPC102LFBN-RC [mil] "Sullins"
  rect 65x65 hole 40: 1(450,-50)
  round 65 hole 40: 2(450,50) 3(350,-50) 4(350,50) 5(250,-50) 6(250,50) 7(150,-50) 8(150,50) 9(50,-50) 10(50,50) 11(-50,-50) 12(-50,50) 13(-150,-50) 14(-150,50) 15(-250,-50) 16(-250,50) 17(-350,-50) 18(-350,50) 19(-450,-50) 20(-450,50)
  silkscreen extent -514,-116 526,104
SW_B3U-1000P [mm] "OMRON"
  rect 0.8x1.7 smd: 1(-1.7,0) 2(1.7,0)
  silkscreen extent -1.5,-1.25 1.5,1.25
SW_TDA04H0SB1 [mil] "C&K Components"
  rect 50x30 smd: 1(-150,75) 2(-150,25) 3(-150,-25) 4(-150,-75) 5(150,-75) 6(150,-25) 7(150,25) 8(150,75)
  silkscreen extent -126,-122 126,122
TI_Stacked_Overlay_Small [mil]
TRANS_NexFET_Q3 [mm] "TI recommended land pattern (nominal) M0143-01"
  rect 0.63x0.5 smd mask+0.075: 1(-1.49,0.975) 2(-1.49,0.325) 3(-1.49,-0.325) 4(-1.49,-0.975) 5(1.38,-0.975) 6(1.38,-0.325) 7(1.38,0.325) 8(1.38,0.975)
  Top Layer region: -0.615,1.225 1.285,1.225 1.285,-1.225 -0.615,-1.225
  silkscreen extent -2.05,-2 2,2
ZQZ0096A_Oval [mm] "BGA, 96-Leads, Body 6.0x6.0mm,  Pitch 0.50mm"
  round 0.275 smd: A1(-2.5,2.5) A11(2.5,2.5) B2(-2,2) B3(-1.5,2) B4(-1,2) B5(-0.5,2) B6(0,2) B7(0.5,2) B8(1,2) B9(1.5,2) B10(2,2) C2(-2,1.5) C10(2,1.5) D2(-2,1) D5(-0.5,1) D6(0,1) D7(0.5,1) D8(1,1) D10(2,1) E2(-2,0.5) E4(-1,0.5) E5(-0.5,0.5) E6(0,0.5) E7(0.5,0.5) E8(1,0.5) E10(2,0.5) F2(-2,0) F4(-1,0) F5(-0.5,0) F6(0,0) F7(0.5,0) F8(1,0) F10(2,0) G2(-2,-0.5) G4(-1,-0.5) G5(-0.5,-0.5) G6(0,-0.5) G7(0.5,-0.5) G8(1,-0.5) G10(2,-0.5) H2(-2,-1) H4(-1,-1) H5(-0.5,-1) H6(0,-1) H7(0.5,-1) H8(1,-1) H10(2,-1) J2(-2,-1.5) J10(2,-1.5) K2(-2,-2) K3(-1.5,-2) K4(-1,-2) K5(-0.5,-2) K6(0,-2) K7(0.5,-2) K8(1,-2) K9(1.5,-2) K10(2,-2) L1(-2.5,-2.5) L11(2.5,-2.5)
  oval 0.178x0.33 smd: A2(-2,2.5) A3(-1.5,2.5) A4(-1,2.5) A5(-0.5,2.5) A6(0,2.5) A7(0.5,2.5) A8(1,2.5) A9(1.5,2.5) A10(2,2.5) L2(-2,-2.5) L3(-1.5,-2.5) L4(-1,-2.5) L5(-0.5,-2.5) L6(0,-2.5) L7(0.5,-2.5) L8(1,-2.5) L9(1.5,-2.5) L10(2,-2.5)
  oval 0.33x0.178 smd: B1(-2.5,2) B11(2.5,2) C1(-2.5,1.5) C11(2.5,1.5) D1(-2.5,1) D11(2.5,1) E1(-2.5,0.5) E11(2.5,0.5) F1(-2.5,0) F11(2.5,0) G1(-2.5,-0.5) G11(2.5,-0.5) H1(-2.5,-1) H11(2.5,-1) J1(-2.5,-1.5) J11(2.5,-1.5) K1(-2.5,-2) K11(2.5,-2)
  silkscreen extent -3,-3 3,3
